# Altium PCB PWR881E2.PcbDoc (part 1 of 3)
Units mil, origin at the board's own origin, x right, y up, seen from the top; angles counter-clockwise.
Board outline 6500 x 3500 mil, 6 copper layers (Top Layer, Signal Layer 1, Signal Layer 2, Signal Layer 3, Signal Layer 4, Bottom Layer), stack 32.4 mil thick; 330 components, 152 nets, 836 pads, 570 vias.
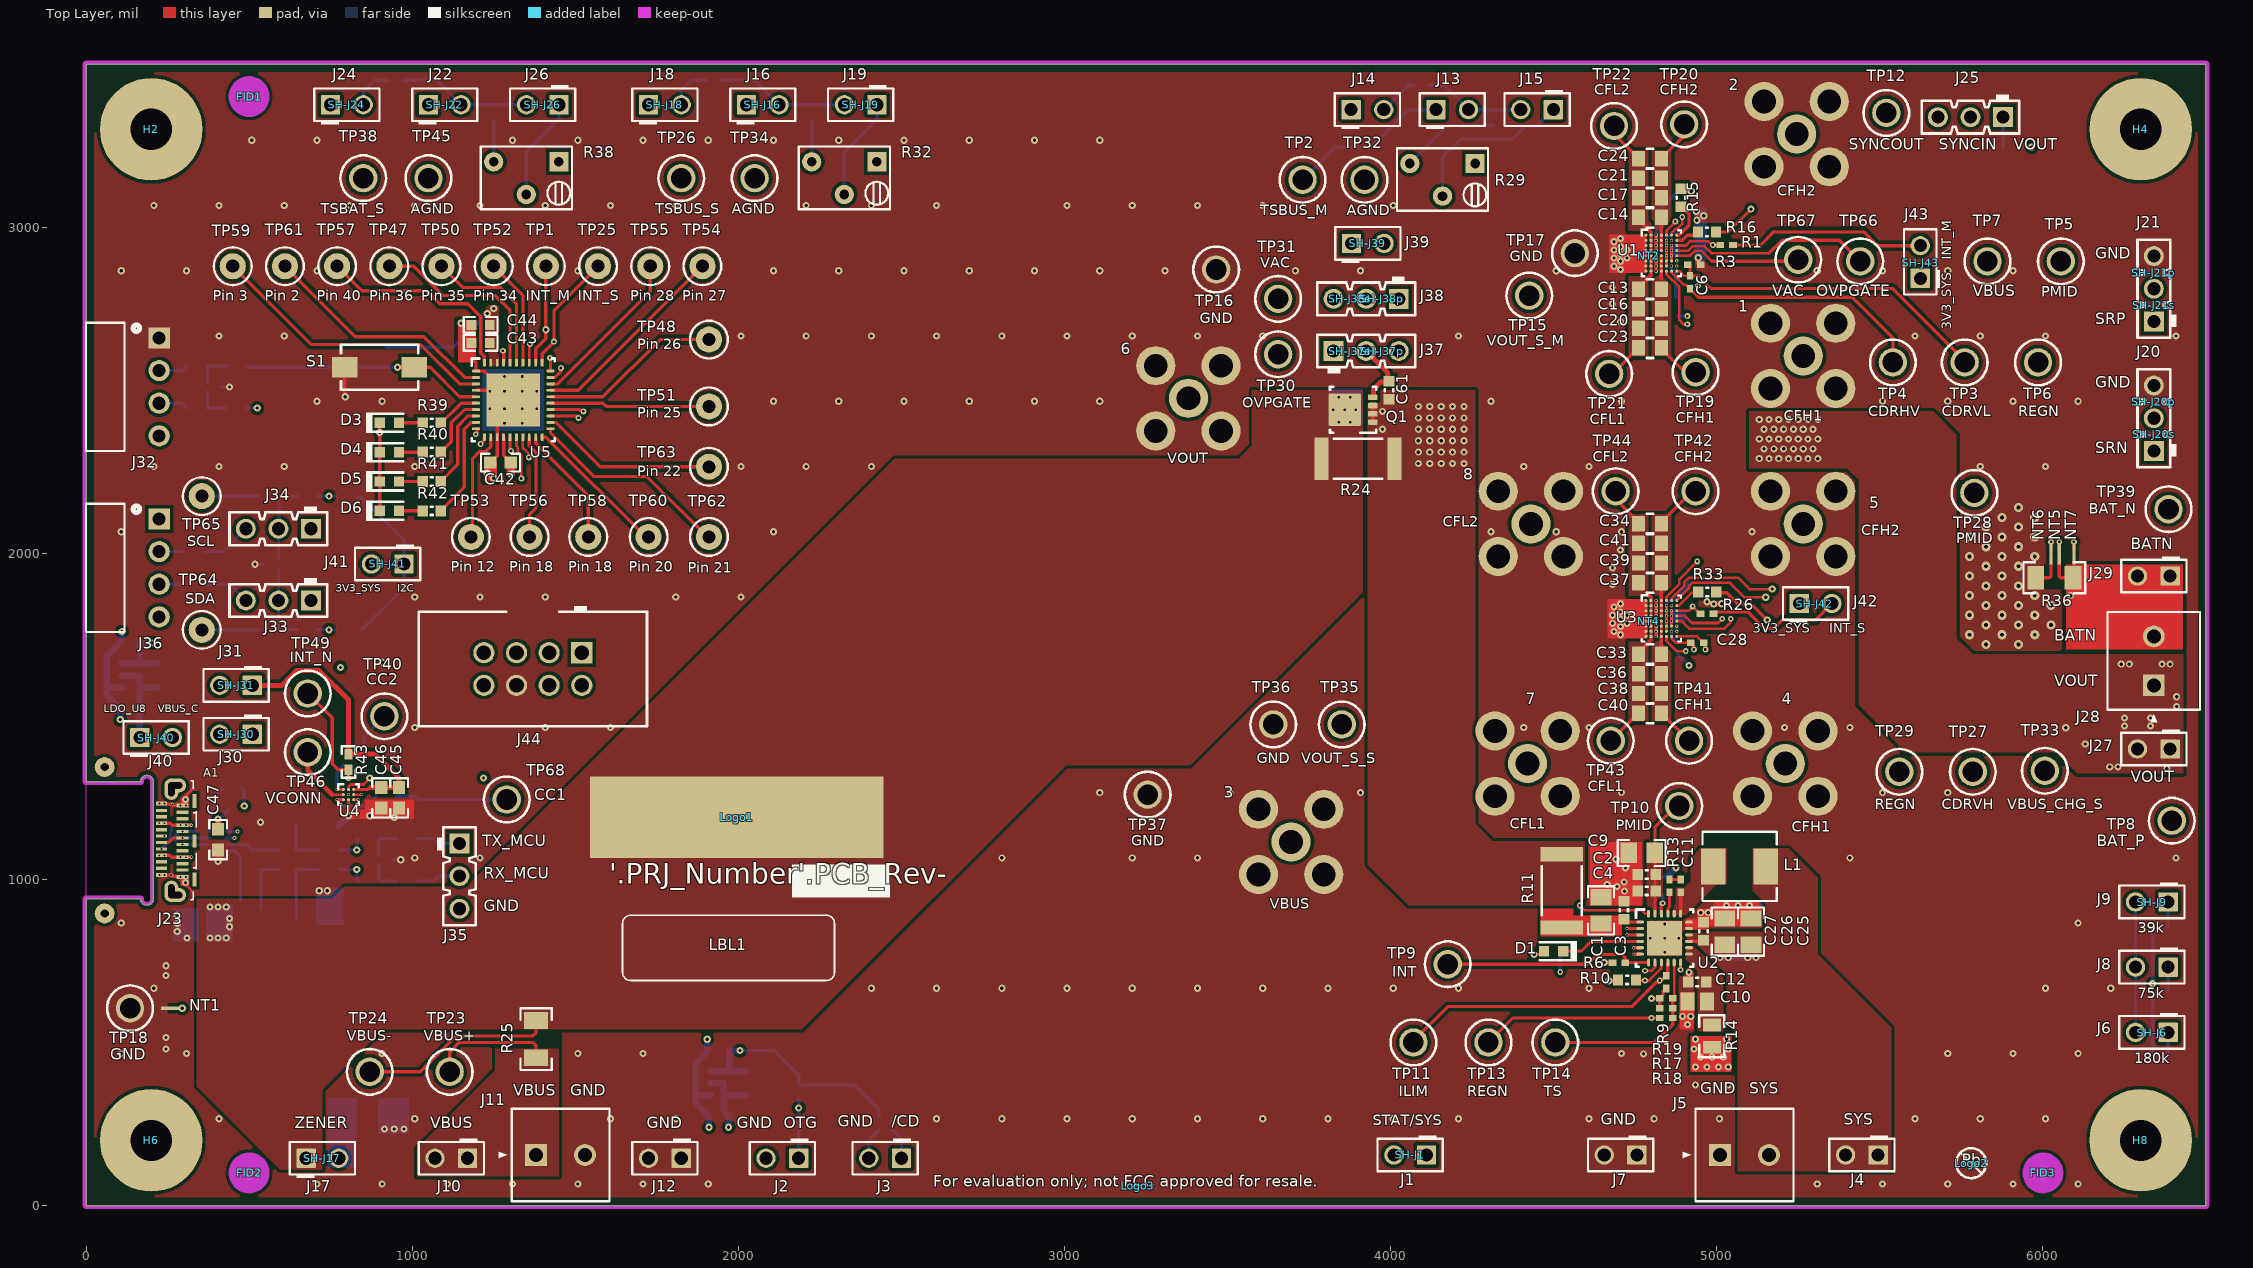
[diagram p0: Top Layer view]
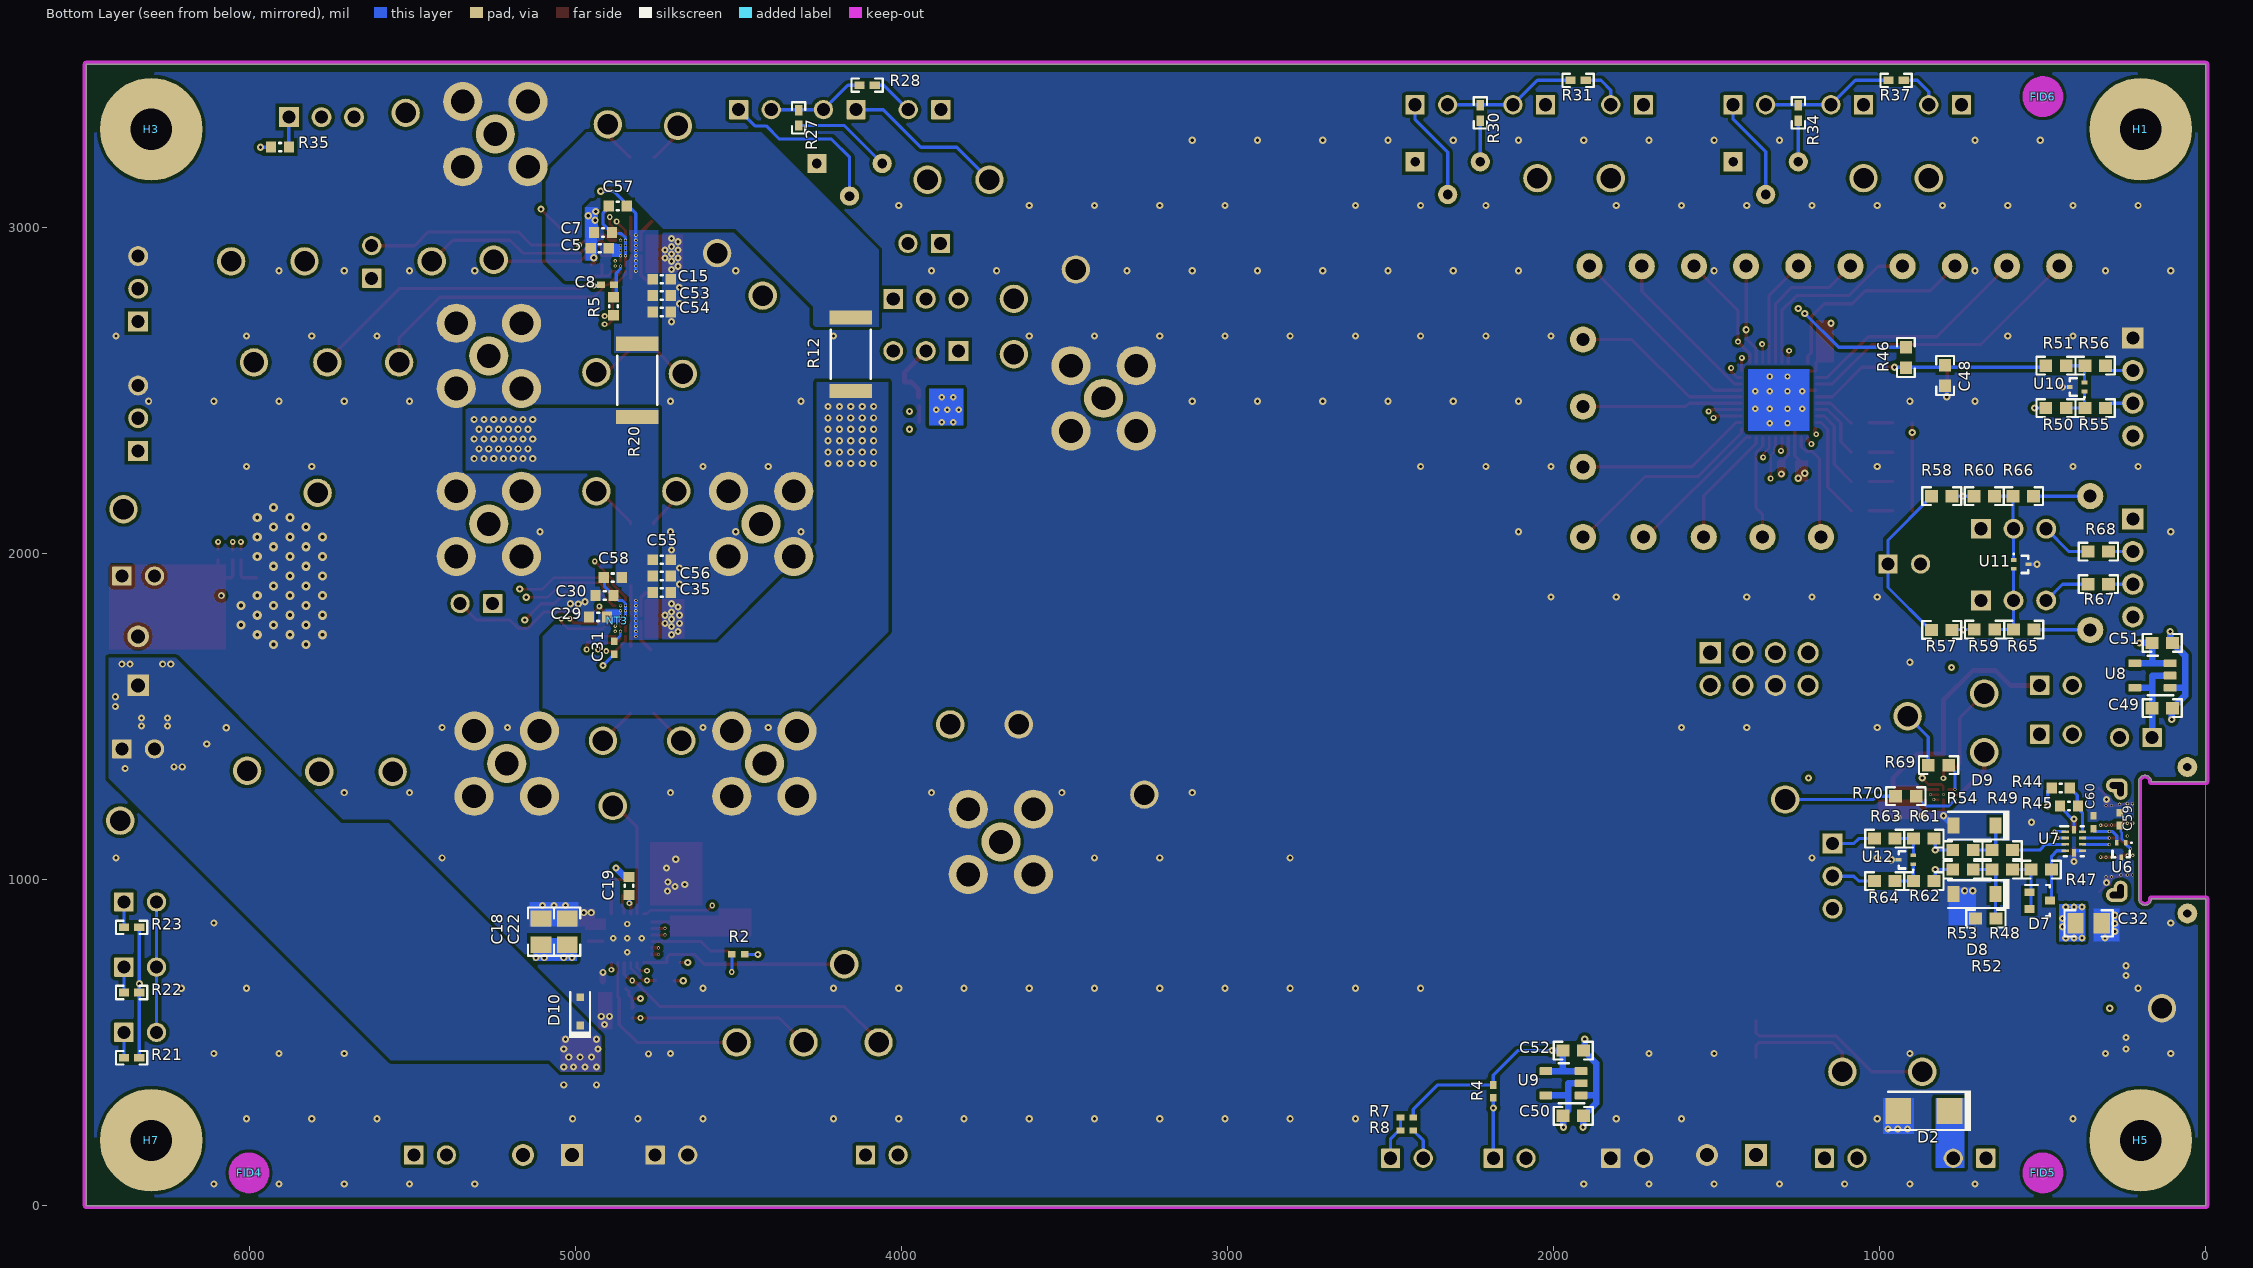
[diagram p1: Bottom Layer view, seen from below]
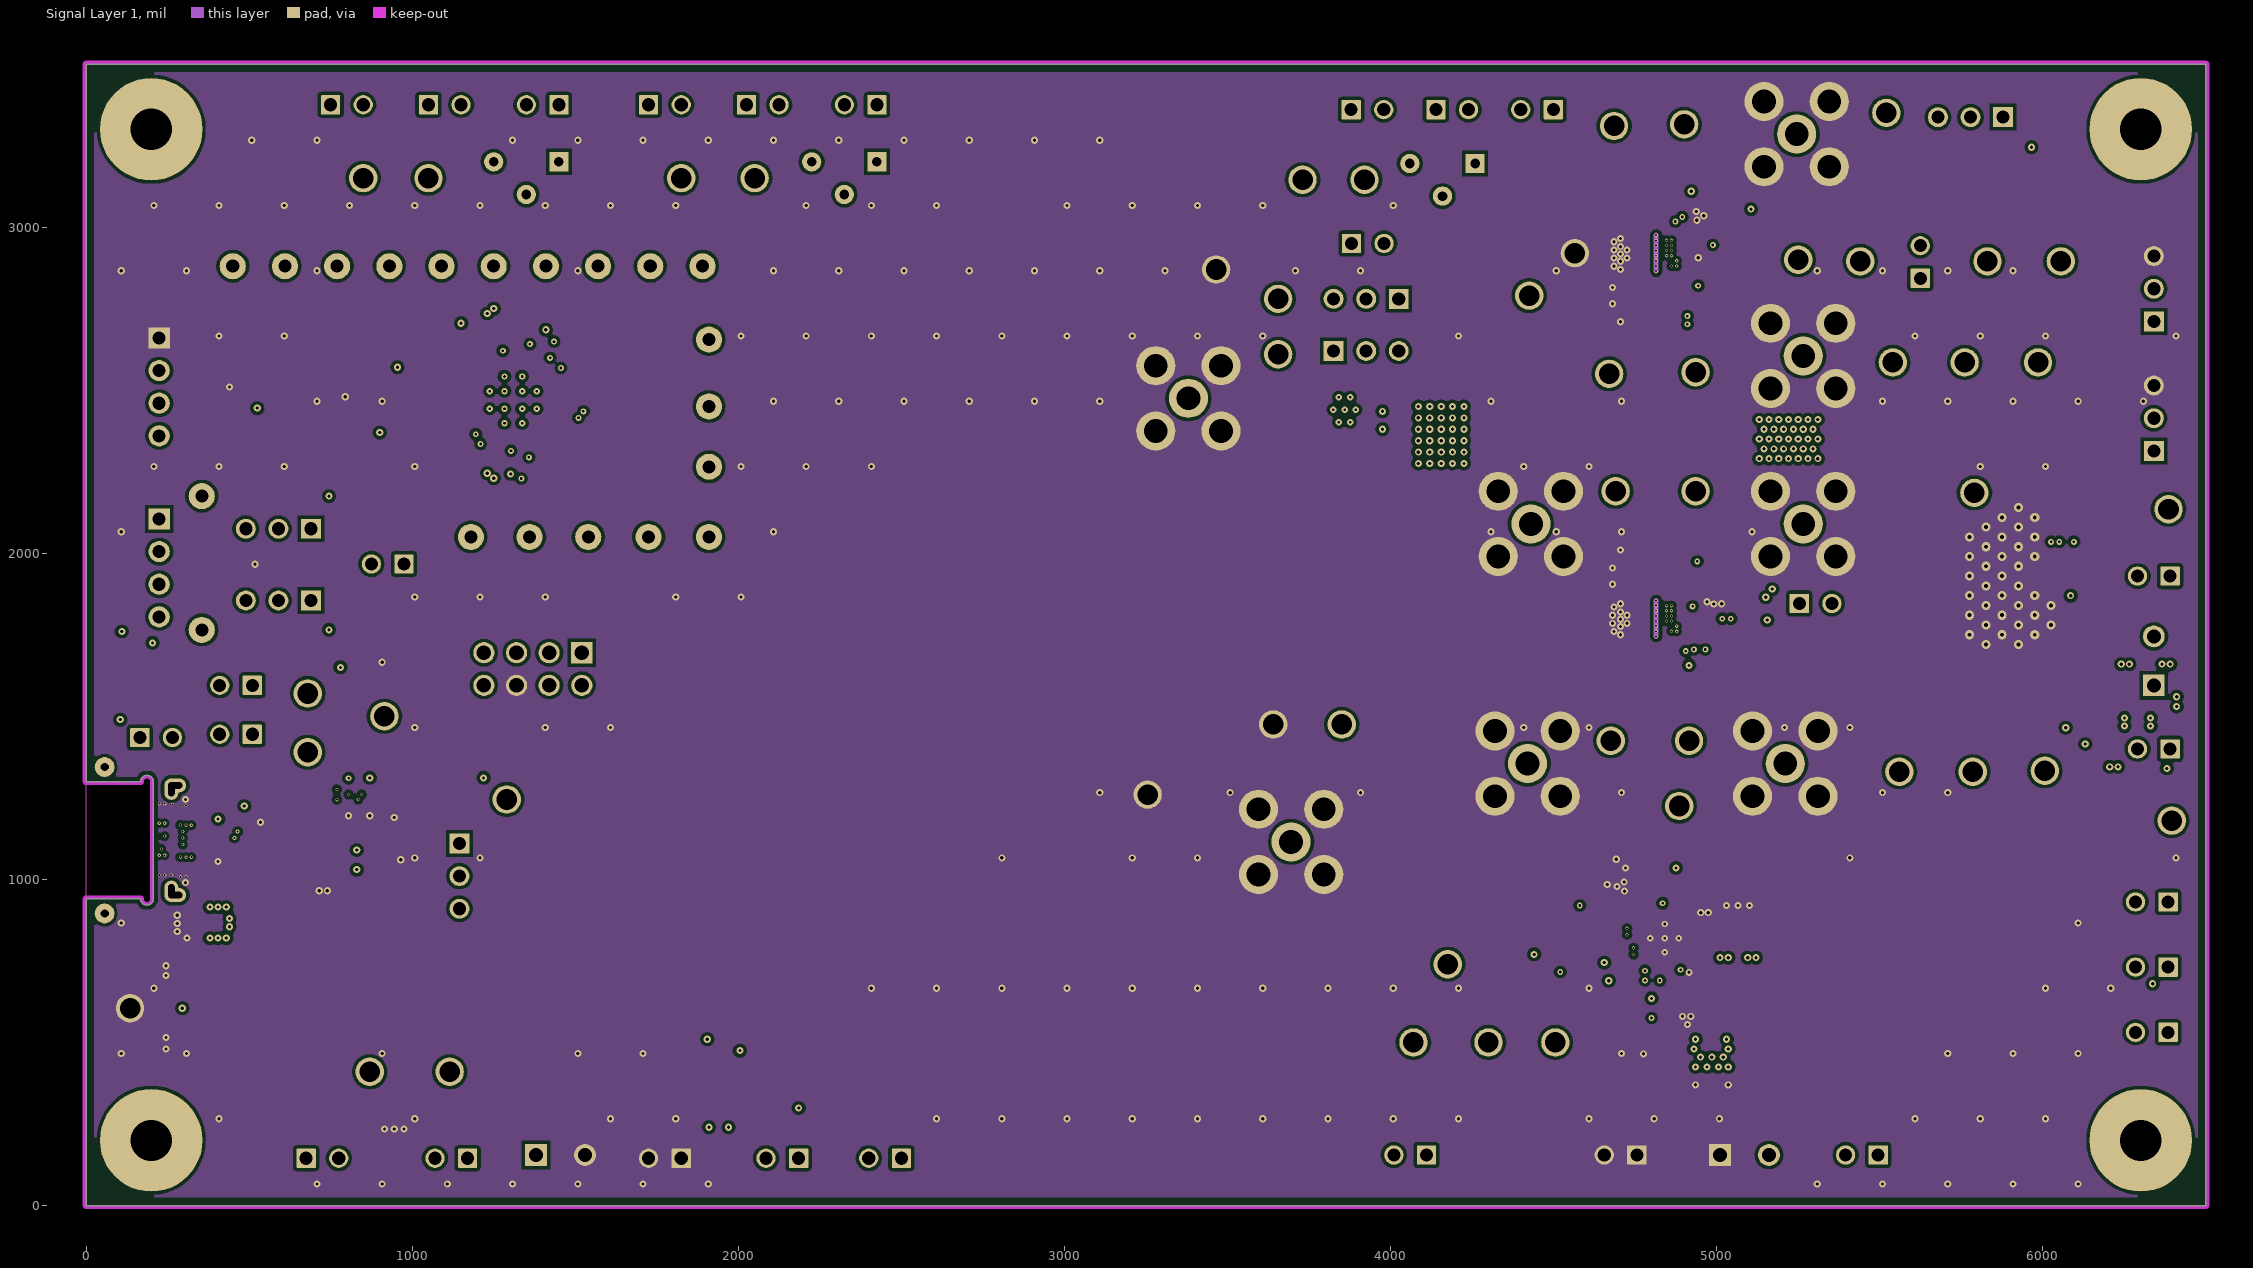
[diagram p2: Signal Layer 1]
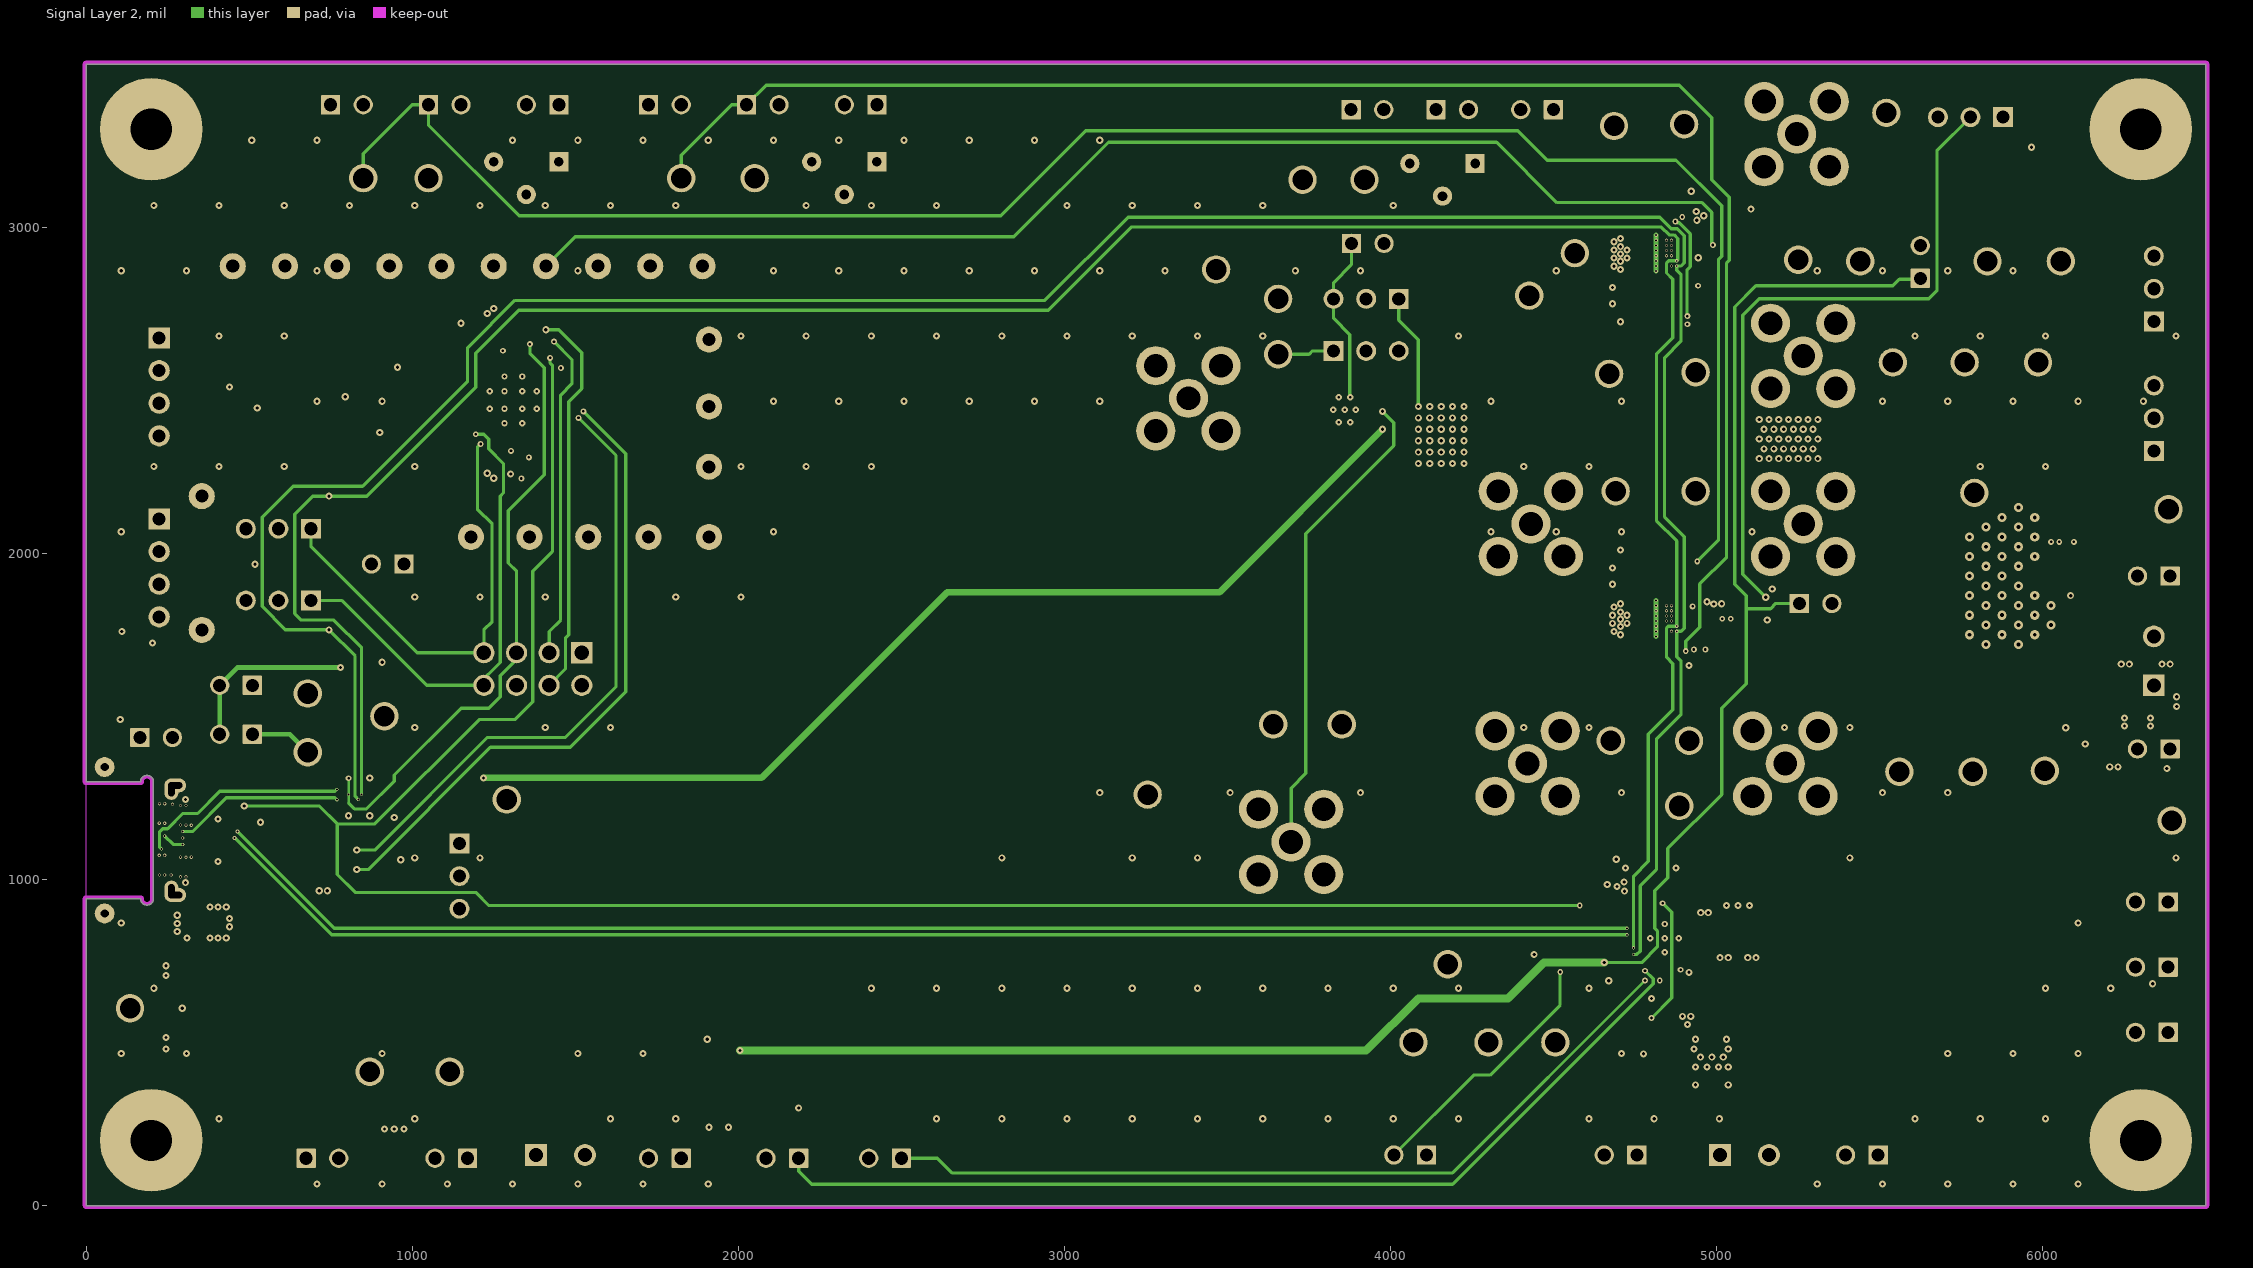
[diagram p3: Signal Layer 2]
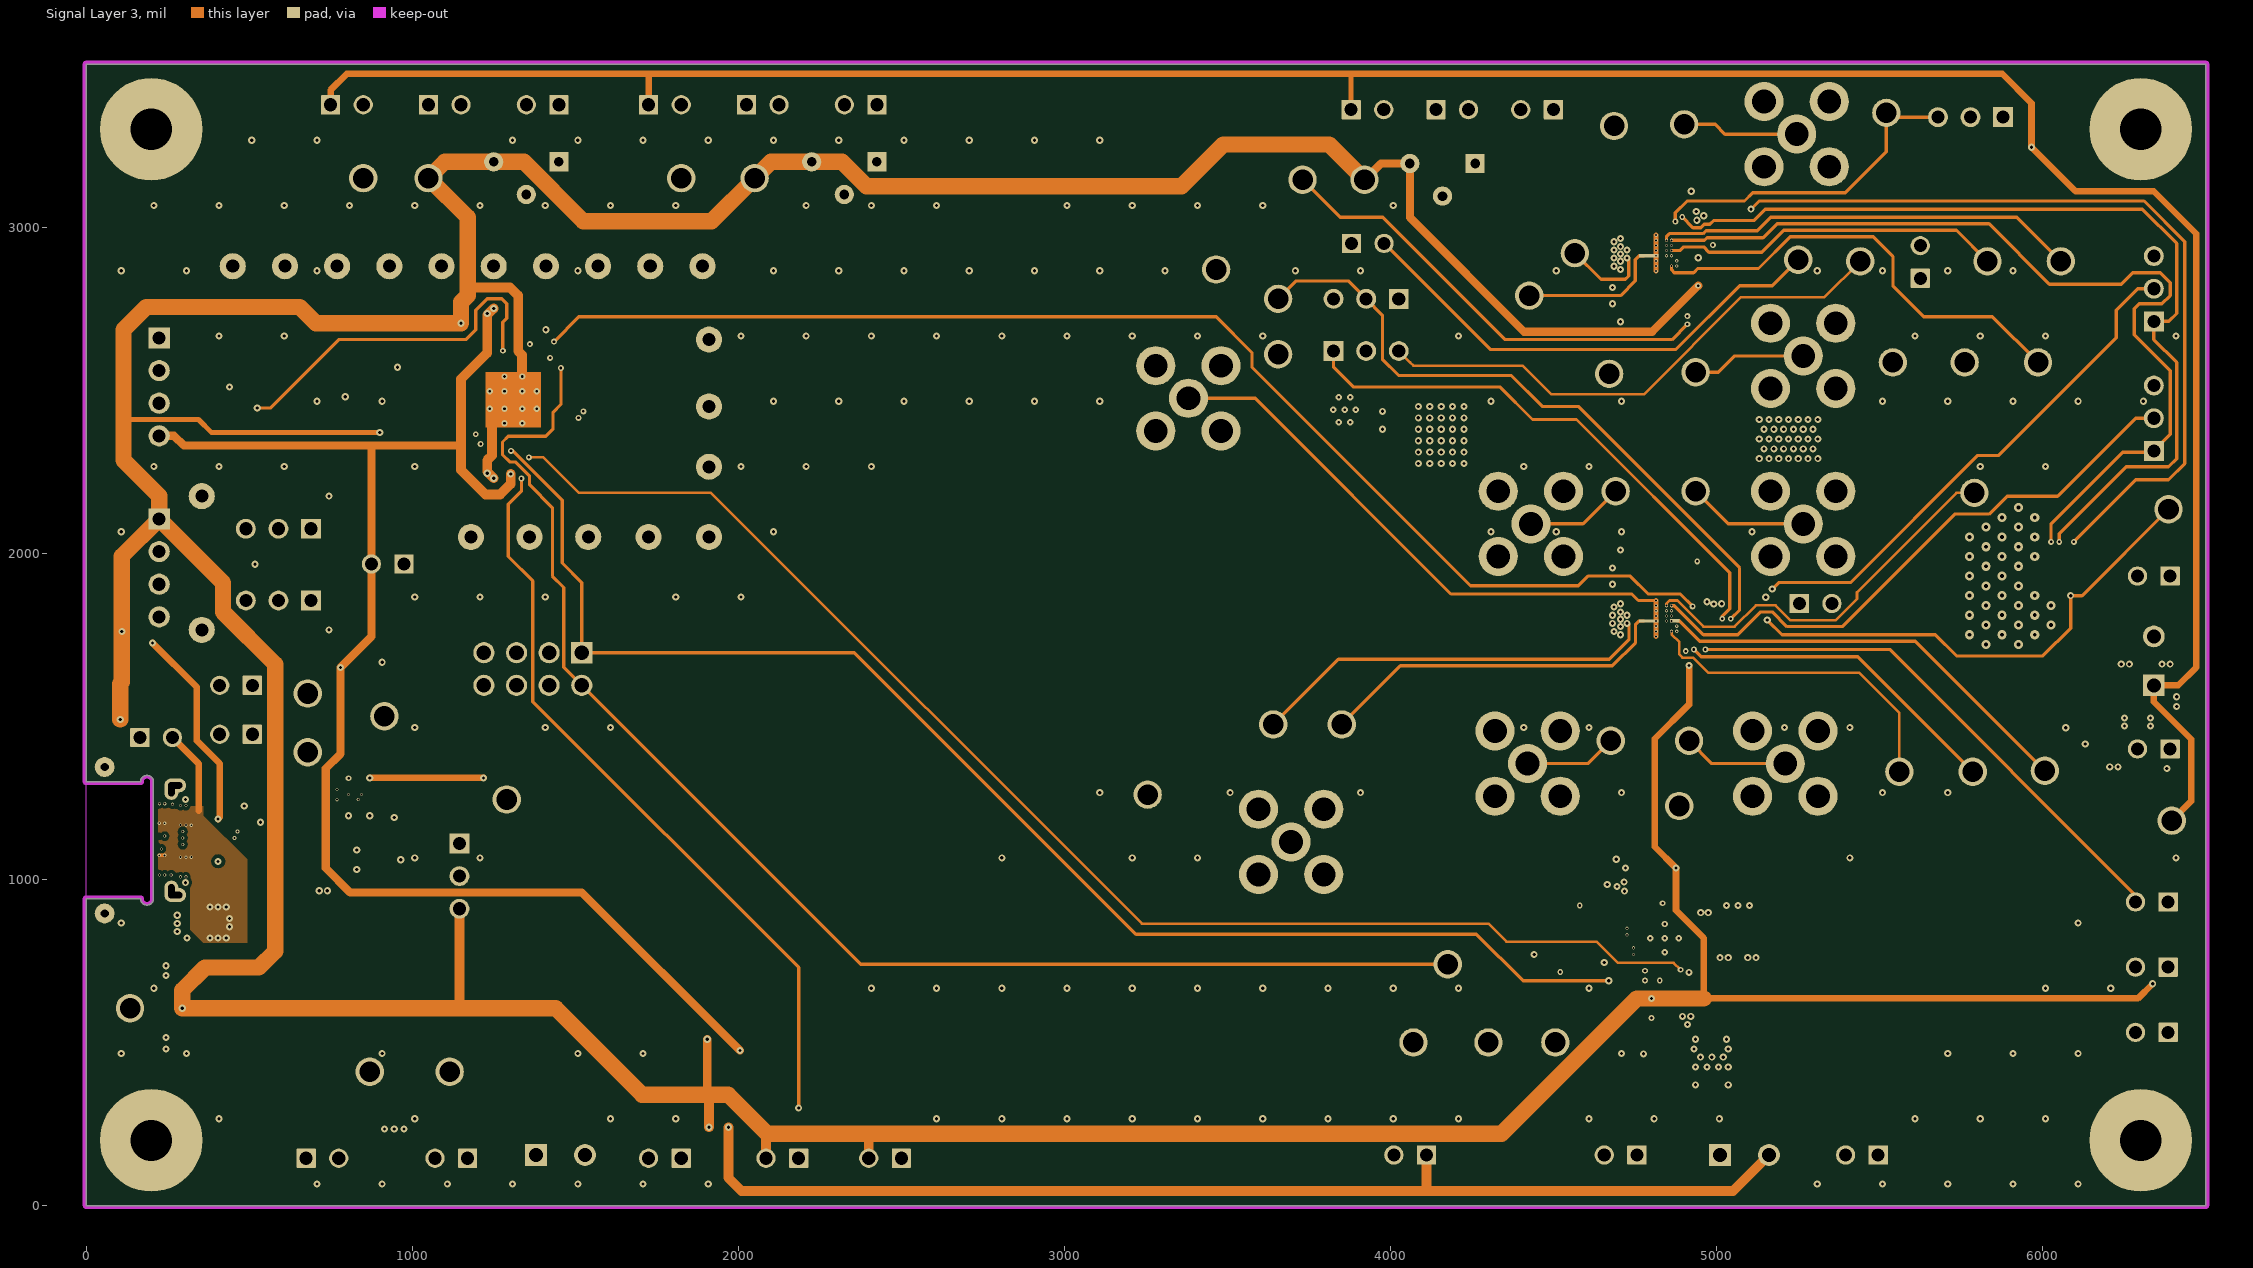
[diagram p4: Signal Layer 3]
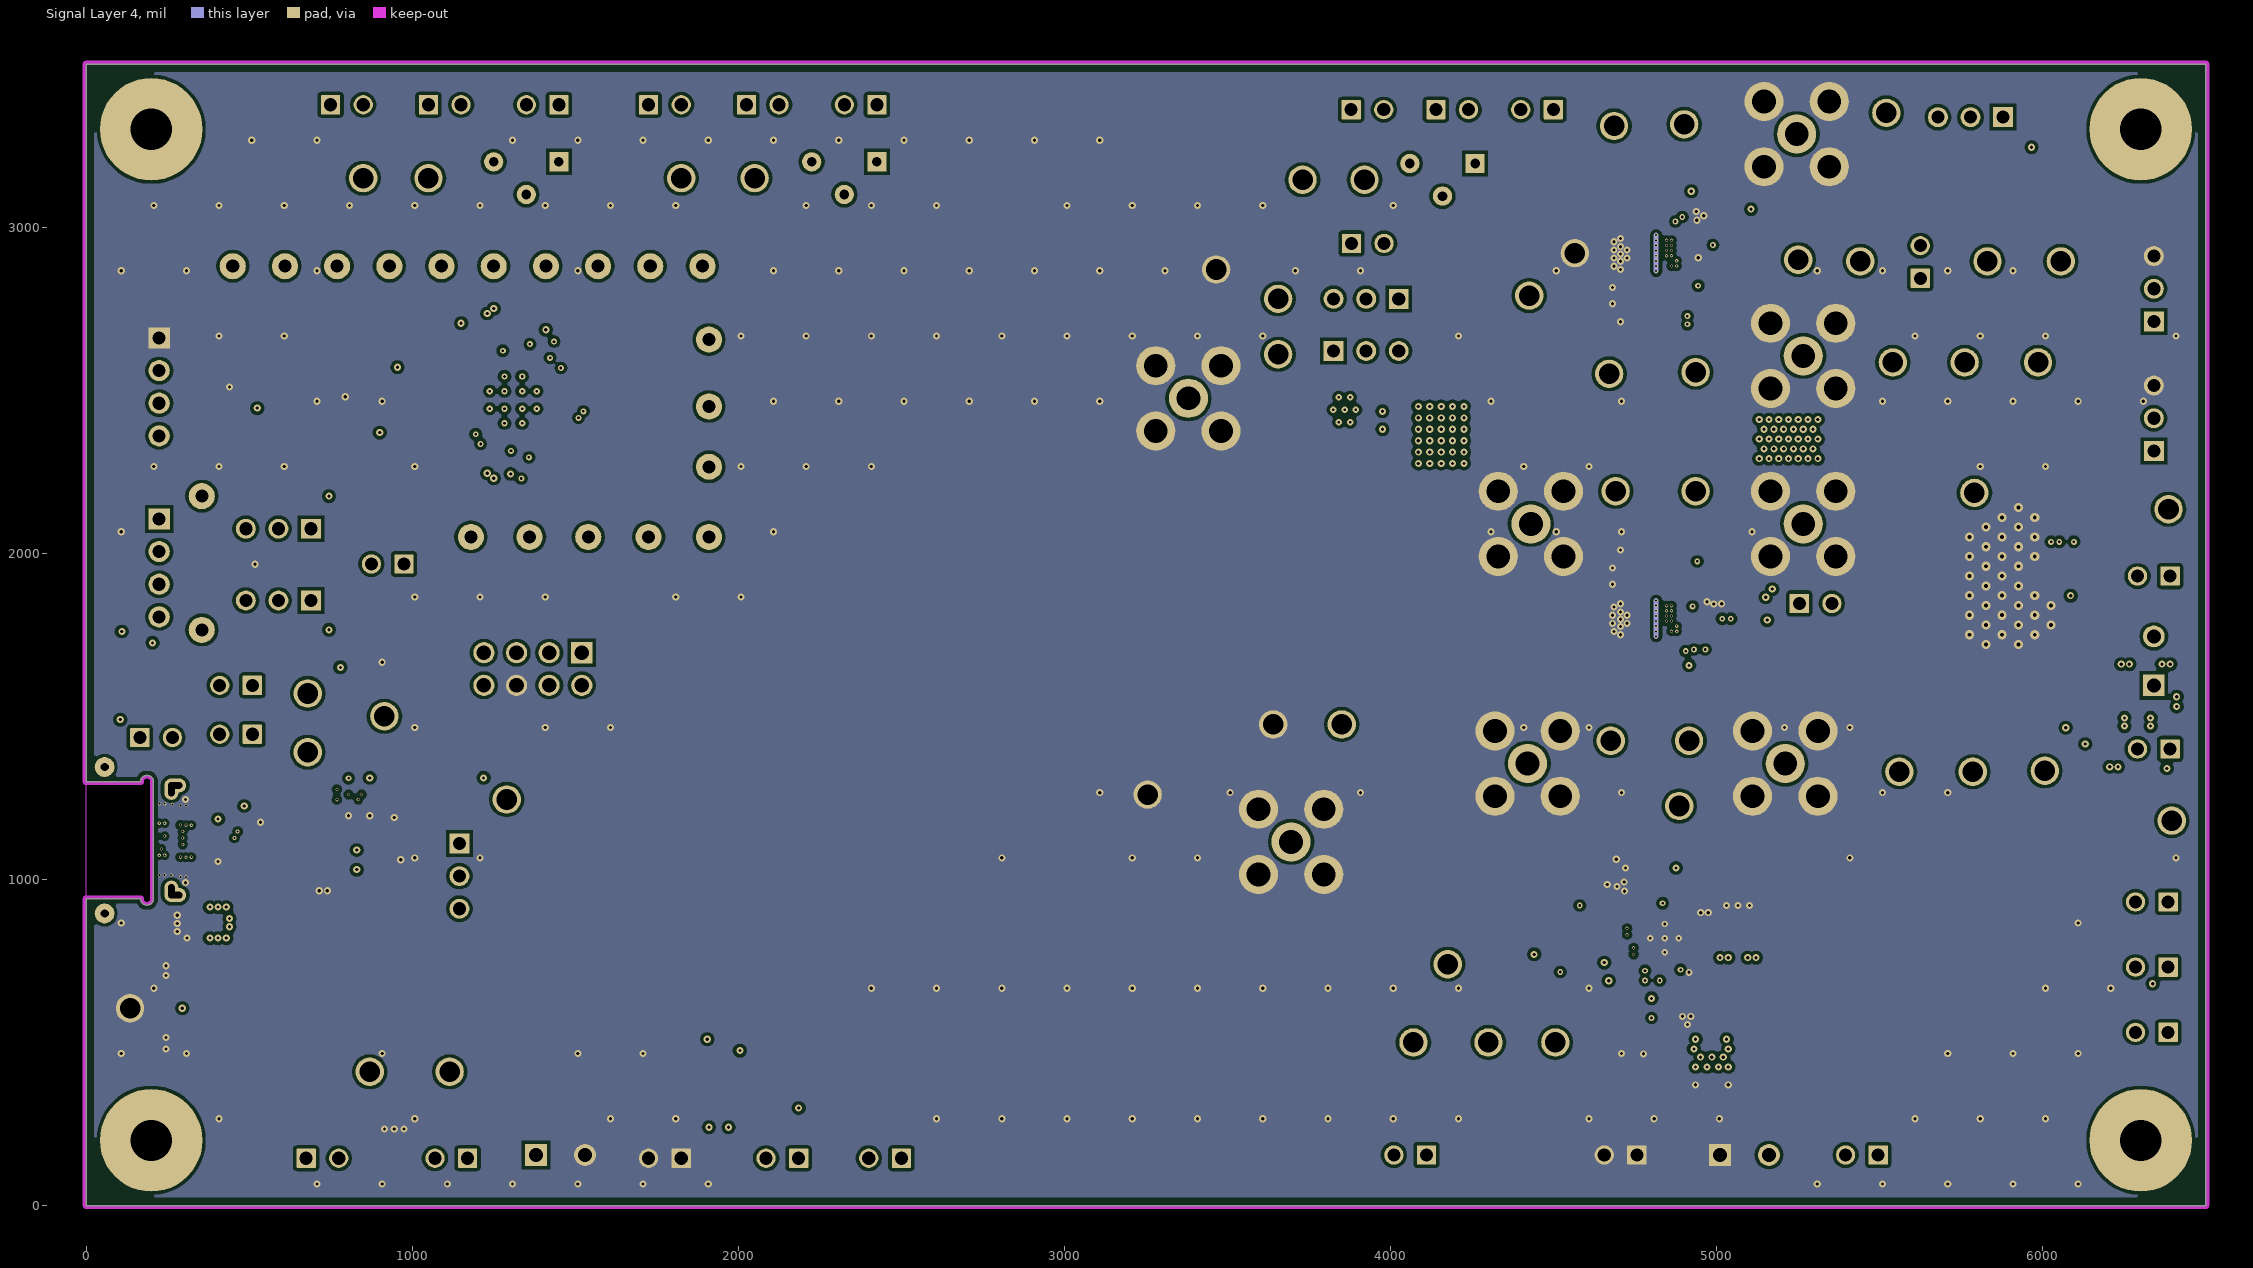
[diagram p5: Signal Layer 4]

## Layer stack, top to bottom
Top Solder: solder mask 0.4, Solder Resist, Dk 3.5
Top Layer: signal copper 1.4
Dielectric1: core 4.8, FR-4 High TG, Dk 4.8
Signal Layer 1: signal copper 1.4
Dielectric 2: prepreg 4.8, FR-4 High TG, Dk 4.8
Signal Layer 2: signal copper 1.4
Dielectric 3: core 4.8, FR-4 High TG, Dk 4.8
Signal Layer 3: signal copper 1.4
Dielectric 4: prepreg 4.8, FR-4 High TG, Dk 4.8
Signal Layer 4: signal copper 1.4
Dielectric 5: core 4.8, FR-4 High TG, Dk 4.8
Bottom Layer: signal copper 1.4
Bottom Solder: solder mask 0.4, Solder Resist, Dk 4.8

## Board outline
0,0 0,940.87 167.32,940.87 ccw(c187.01,940.87) 206.69,940.87 206.69,1299.13 ccw(c187.01,1299.13) 167.32,1299.13 0,1299.13 0,3500 6500,3500 6500,0

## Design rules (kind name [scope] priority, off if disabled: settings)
AcuteAngle [All] p1: minimum=4.50000000000000E+0001 checktracksonly=FALSE
AssemblyTestPointUsage [All] p1: valid=2
BoardOutlineClearance BoardOutlineClearance_J23 [InComponent('J23')] p1: gap=7.8
BoardOutlineClearance BoardOutlineClearance_MountingHoles [OnCopper and InComponentClass('Mounting Holes')] p2: gap=40
BoardOutlineClearance BoardOutlineClearance_Poly [OnCopper and IsPoly] p3: gap=15
BoardOutlineClearance [OnCopper and Not InComponentClass('Logo') and not InComponentClass('FiducialMark') and not InRegion(1000,500,4000,800) and not InPoly] p4: gap=12.8
Clearance Clearance_Keepouts [((IsTrack Or IsArc) And Not InPoly) And IsFree and IsKeepOut vs ((IsTrack Or IsArc) And Not InPoly) And IsFree and IsKeepOut] p1: gap=0
Clearance Clearance_Poly [InPolygon] p2: gap=10
Clearance [All] p3: gap=5.7
ComponentClearance ComponentClearance_NT [InComponent('NT*')] p1: gap=0 collisioncheckmode=3 verticalgap=0 showdistances=FALSE
ComponentClearance ComponentClearance_MountingHoles_FiducialMarks [InComponentClass('Mounting Holes') vs InComponentClass('FiducialMark')] p2: gap=50 collisioncheckmode=3 verticalgap=10 showdistances=FALSE
ComponentClearance ComponentClearance_Shunt [InComponentClass('Header')   or InComponentClass('Shunt') vs InComponentClass('Shunt')] p3: gap=0 collisioncheckmode=3 verticalgap=0 showdistances=FALSE
ComponentClearance ComponentClearance_Logo [InComponentClass('Logo')] p4: gap=50 collisioncheckmode=3 verticalgap=10 showdistances=FALSE
ComponentClearance ComponentClearance_ScrewToNut [(HasFootprint('NY PMS 440 0025 PH')) vs (HasFootprint('Keystone_1902C'))] p5: gap=5 collisioncheckmode=3 verticalgap=10 showdistances=FALSE
ComponentClearance ComponentClearance_MountingHoles [InComponentClass('Mounting Holes')] p6: gap=100 collisioncheckmode=3 verticalgap=100000 showdistances=FALSE
ComponentClearance ComponentClearance_SmallPassives [HasFootprint('0201*') or HasFootprint('0402*') or HasFootprint('0508') or HasFootprint('0603*') or HasFootprint('0612') or HasFootprint('0805*') or HasFootprint('0815*') or HasFootprint('0830*') or HasFootprint('1206*') or HasFootprint('1210*') or HasFootprint('1808*') or HasFootprint('1812*') or HasFootprint('1825*') or HasFootprint('2010*') or HasFootprint('2220*') or HasFootprint('2225*') or HasFootprint('2512*') or HasFootprint('2728*') or HasFootprint('3518*') vs HasFootprint('0201*') or HasFootprint('0402*') or HasFootprint('0508') or HasFootprint('0603*') or HasFootprint('0612') or HasFootprint('0805*') or HasFootprint('0815*') or HasFootprint('0830*') or HasFootprint('1206*') or HasFootprint('1210*') or HasFootprint('1808*') or HasFootprint('1812*') or HasFootprint('1825*') or HasFootprint('2010*') or HasFootprint('2220*') or HasFootprint('2225*') or HasFootprint('2512*') or HasFootprint('2728*') or HasFootprint('3518*')] p7: gap=5 collisioncheckmode=3 verticalgap=5 showdistances=FALSE
ComponentClearance ComponentClearance_THtoSMT [IsThruComponent vs IsSMTComponent] p8: gap=30 collisioncheckmode=3 verticalgap=30 showdistances=FALSE
ComponentClearance ComponentClearance_THtoTH [IsThruComponent vs IsThruComponent] p9: gap=30 collisioncheckmode=3 verticalgap=30 showdistances=FALSE
ComponentClearance [All] p10: gap=15 collisioncheckmode=3 verticalgap=15 showdistances=FALSE
DiffPairsRouting [All] p1: maxlimit=100 minlimit=10 mostfreqgap=10 toplayer_minwidth=15 toplayer_maxwidth=15 toplayer_prefwidth=15 midlayer1_minwidth=15 midlayer1_maxwidth=15 midlayer1_prefwidth=15 midlayer2_minwidth=15 midlayer2_maxwidth=15 midlayer2_prefwidth=15 midlayer3_minwidth=15 midlayer3_maxwidth=15 midlayer3_prefwidth=15 midlayer4_minwidth=15 midlayer4_maxwidth=15 midlayer4_prefwidth=15 bottomlayer_minwidth=15 bottomlayer_maxwidth=15 bottomlayer_prefwidth=15 maxuncoupledlength=1000
FabricationTestPointUsage TestPointUsage [All] p1: valid=2 allowmultiple=FALSE
FabricationTestpoint Testpoint [All] p1: side=3 testpointundercomponent=TRUE minsize=40 maxsize=100 preferedsize=60 minholesize=0 maxholesize=40 preferedholesize=32 testpointgrid=1 allowsidetop=TRUE allowsidebottom=TRUE usegrid=TRUE gridtolerance=0.01
FanoutControl Fanout_LCC [IsLCC] p1: bgadir=Out bgaviamode=Centered fanoutstyle=Auto fanoutdirection=Alternating viagrid=1 // Fanout_LCC (Default Rule)
FanoutControl Fanout_BGA [IsBGA] p2: bgadir=Out bgaviamode=Centered fanoutstyle=Auto fanoutdirection=Alternating viagrid=1 // Fanout_BGA (Default Rule)
FanoutControl Fanout_Default [All] p4: bgadir=Out bgaviamode=Centered fanoutstyle=Auto fanoutdirection=Alternating viagrid=1 // Fanout_Default (Default Rule)
FanoutControl Fanout_Small [(CompPinCount < 5)] p5: bgadir=Out bgaviamode=Centered fanoutstyle=Auto fanoutdirection=OutThenIn viagrid=1 // Fanout_Small (Default Rule)
HoleSize [All] p1: absolutevalues=TRUE maxlimit=251 minlimit=6 maxpercent=80.000 minpercent=20.000
HoleToHoleClearance HoleToHoleClearance_J23 [InComponent('J23') vs InComponent('J23')] p1: gap=0 allowstackedmicrovias=TRUE
HoleToHoleClearance [All] p2: gap=9.7 allowstackedmicrovias=TRUE
MinimumAnnularRing MinimumAnnularRing_ThermalPadVias [IsVia and InAnyComponent] p1: minimumring=5.91
MinimumAnnularRing [All] p2: minimumring=2
MinimumSolderMaskSliver MinimumSolderMaskSliver_YFF0056ACAJ [HasFootprint('YFF0056ACAJ')] p1: minsoldermaskwidth=3.7
MinimumSolderMaskSliver MinimumSolderMaskSliver_Logo [InComponentClass('Logo') vs InComponentClass('Logo')] p2: minsoldermaskwidth=0.7
MinimumSolderMaskSliver [All] p3: minsoldermaskwidth=3.94
PlaneConnect [All] p1: planeconnectstyle=Relief reliefexpansion=10 reliefentries=4 reliefconductorwidth=10 reliefairgap=10
PolygonConnect [All] p1: connectstyle=Direct reliefconductorwidth=10 reliefentries=4 polygonreliefangle="90 Angle" airgapwidth=10
RoutingVias ThermalPadVias [IsVia and InAnyComponent] p1: holewidth=7.87 width=19.68 viastyle="Through Hole" minholewidth=7.87 minwidth=19.68 maxholewidth=12.99 maxwidth=23.62
RoutingVias [All] p2: holewidth=10 width=22 viastyle="Through Hole" minholewidth=6 minwidth=6 maxholewidth=40 maxwidth=65
ShortCircuit ShortCircuit_j23 [InComponent('J23') vs InComponent('J23')] p1: allowed=TRUE
ShortCircuit [All] p2: allowed=FALSE
SilkToBoardRegionClearance [Not ((IsComment or IsDesignator) And (Hide <> 'False')) and not InRegion(1000,500,4000,800)] p1:
SilkToSilkClearance SilkToSilkClearance_Pb-FreeLogo [(HasFootprint('Pb-Free_Overlay_Medium') OR HasFootprint('Pb-Free_Overlay_Small')) vs (HasFootprint('Pb-Free_Overlay_Medium') OR HasFootprint('Pb-Free_Overlay_Small'))] p1: silktosilkclearance=0
SilkToSilkClearance [All] p2: silktosilkclearance=4
SilkToSolderMaskClearance SilkToComponentPadClearance [IsPad and InAnycomponent] p1: minsilkscreentomaskgap=4 clearancetoexposedcopper=TRUE
SilkToSolderMaskClearance "Silk to Solder Mask Opening" [All] p2: minsilkscreentomaskgap=4 clearancetoexposedcopper=FALSE
SolderMaskExpansion [All] p1: expansion=1.97
Width [All] p1: maxlimit=100 minlimit=7.8 preferedwidth=10 checkconnectedcopper=TRUE
13 further rules are at their usual default settings.

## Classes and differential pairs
component class "Mounting Holes": H2 H4 H6 H8
component class Logo: Logo1
component class PWR881E2_EVM_Hardware: FID1 FID2 FID3 FID4 FID5 FID6 H1 H2 H3 H4 H5 H6 H7 H8 LBL1 Logo1 Logo2 Logo3 SH-J1 SH-J6 SH-J9 SH-J16 SH-J17 SH-J18 SH-J19 SH-J20p SH-J20s SH-J21p SH-J21s SH-J22 SH-J24 SH-J26 SH-J30 SH-J31 SH-J37p SH-J37s SH-J38p SH-J38s SH-J39 SH-J40 SH-J41 SH-J42 SH-J43 ZZ1 ZZ2 ZZ3 ZZ4
component class FiducialMark: FID1 FID2 FID3 FID4 FID5 FID6
component class AssemblyNote: ZZ1 ZZ2 ZZ3 ZZ4
component class Label: LBL1
component class Header: J1 J2 J3 J4 J6 J7 J8 J9 J10 J12 J13 J14 J15 J16 J17 J18 J19 J20 J21 J22 J24 J25 J26 J27 J29 J30 J31 J33 J34 J35 J37 J38 J39 J40 J41 J42 J43
component class PWR881E2_MCU_USB: C42 C43 C44 C45 C46 C47 C48 C49 C50 C51 C52 C59 C60 D3 D4 D5 D6 D7 D8 D9 J30 J31 J32 J33 J34 J35 J36 J40 J41 J44 R39 R40 R41 R42 R43 R44 R45 R46 R47 R48 R49 R50 R51 R52 R53 R54 R55 R56 R57 R58 R59 R60 R61 R62 R63 R64 R65 R66 R67 R68 R69 R70 S1 TP40 TP46 TP47 TP48 TP49 TP50 TP51 TP52 TP53 TP54 TP55 TP56 TP57 TP58 TP59 TP60 TP61 TP62 TP63 TP64 TP65 TP68 U4 U5 U6 U7 U8 U9 U10 U11 U12
component class PWR881E2: 1 2 3 4 5 6 7 8 C1 C2 C3 C4 C5 C6 C7 C8 C9 C10 C11 C12 C13 C14 C15 C16 C17 C18 C19 C20 C21 C22 C23 C24 C25 C26 C27 C28 C29 C30 C31 C32 C33 C34 C35 C36 C37 C38 C39 C40 C41 C53 C54 C55 C56 C57 C58 C61 D1 D2 D10 J1 J2 J3 J4 J5 J6 J7 J8 J9 J10 J11 J12 J13 J14 J15 J16 J17 J18 J19 J20 J21 J22 J23 J24 J25 J26 J27 J28 J29 J37 J38 J39 J42 J43 L1 NT1 NT2 NT3 NT4 NT5 NT6 NT7 Q1 R1 R2 R3 R4 R5 R6 R7 R8 R9 R10 R11 R12 R13 R14 R15 R16 R17 R18 R19 R20 R21 R22 R23 R24 R25 R26 R27 R28 R29 R30 R31 R32 R33 R34 R35 R36 R37 R38 TP1 TP2 TP3 TP4 TP5 TP6 TP7 TP8 TP9 TP10 TP11 TP12 TP13 TP14 TP15 TP16 TP17 TP18 TP19 TP20 TP21 TP22 TP23 TP24 TP25 TP26 TP27 TP28 TP29 TP30 TP31 TP32 TP33 TP34 TP35 TP36 TP37 TP38 TP39 TP41 TP42 TP43 TP44 TP45 TP66 TP67 U1 U2 U3
component class Shunt: SH-J1 SH-J6 SH-J9 SH-J16 SH-J17 SH-J18 SH-J19 SH-J20p SH-J20s SH-J21p SH-J21s SH-J22 SH-J24 SH-J26 SH-J30 SH-J31 SH-J37p SH-J37s SH-J38p SH-J38s SH-J39 SH-J40 SH-J41 SH-J42 SH-J43

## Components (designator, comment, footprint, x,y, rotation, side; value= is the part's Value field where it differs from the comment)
1 "CFH1" PROBE 5265,2605 r90 top
2 "CFH2" PROBE 5245,3285 r90 top
3 "VBUS" PROBE 3695,1115 r90 top
4 "CFH1" PROBE 5210,1355 r90 top
5 "CFH2" PROBE 5265,2090 r90 top
6 "VOUT" PROBE 3380,2475 r90 top
7 "CFL1" PROBE 4420,1355 r90 top
8 "CFL2" PROBE 4430,2090 r90 top
C1 "GRM219R71E105KA88D" 0805_HV 4645,905 r90 top
C2 "GRM188R61E106MA73D" 0603L 4785,1015 r180 top
C3 "GRM1885C1E102JA01D" 0603L 4715,905 r90 top
C4 "GRM188R61E106MA73D" 0603L 4785,965 r180 top
C5 "GRM188R61E105KA12D" 0603L 4925,2935 r180 bottom
C6 "GRM155R71C224KA12D" 0402L 4918,2831 r90 top
C7 "GRM188D71A106MA73D" 0603L 4915,2983 r0 bottom
C8 "GRM155R61A475MEAAD" 0402L 4901,2823 r0 bottom
C9 "GRM21BR61E226ME44L" 0805_HV 4770,1081 r180 top
C10 "GRM21BR71A106KE51L" 0805L 4940,625 r180 top
C11 "GRM155R71E473KA88D" 0402L 4890,980 r270 top
C12 "C1608X7R1C105K080AC" 0603L 4940,685 r180 top
C13 "GRMJN7R61C206ME05" 0704 4795,2810 r180 top
C14 "GRMJN7R61C206ME05" 0704 4795,3030 r180 top
C15 "GRM188R61A226ME15D" 0603L 4735,2840 r180 bottom
C16 "GRMJN7R61C206ME05" 0704 4795,2750 r180 top
C17 "GRMJN7R61C206ME05" 0704 4795,3090 r180 top
C18 "GRM21BR71A106KE51L" 0805_HV 5105,840 r90 bottom
C19 "GRM188R61C475KAAJ" 0603L 4835,980 r90 bottom
C20 "GRMJN7R61C206ME05" 0704 4795,2690 r180 top
C21 "GRMJN7R61C206ME05" 0704 4795,3150 r180 top
C22 "GRM21BR71A106KE51L" 0805_HV 5025,840 r90 bottom
C23 "GRMJN7R61C206ME05" 0704 4795,2630 r180 top
C24 "GRMJN7R61C206ME05" 0704 4795,3210 r180 top
C25 "GRM21BR71A106KE51L" 0805_HV 5105,840 r90 top
C26 "GRM21BR71A106KE51L" 0805_HV 5025,840 r90 top
C27 "C1608X7R1E104K080AA" 0603L 4959,841 r90 top
C28 "GRM155R71C224KA12D" 0402L 4940,1725 r0 top
C29 "GRM188R61E105KA12D" 0603L 4930,1805 r180 bottom
C30 "GRM188D71A106MA73D" 0603L 4910,1870 r0 bottom
C31 "GRM155R61A475MEAAD" 0402L 4880,1710 r270 bottom
C32 "C2012X5R1E106K125AB" 0805_HV 360,865 r180 bottom
C33 "GRMJN7R61C206ME05" 0704 4795,1690 r180 top
C34 "GRMJN7R61C206ME05" 0704 4795,2090 r180 top
C35 "GRM188R61A226ME15D" 0603L 4735,1880 r180 bottom
C36 "GRMJN7R61C206ME05" 0704 4795,1630 r180 top
C37 "GRMJN7R61C206ME05" 0704 4795,1910 r180 top
C38 "GRMJN7R61C206ME05" 0704 4795,1570 r180 top
C39 "GRMJN7R61C206ME05" 0704 4795,1970 r180 top
C40 "GRMJN7R61C206ME05" 0704 4795,1510 r180 top
C41 "GRMJN7R61C206ME05" 0704 4795,2030 r180 top
C42 "C1608X7R1E104K080AA" 0603 1271,2278 r180 top
C43 "C1608X7R1E104K080AA" 0603_HV 1210,2645 r180 top
C44 "C1608X7R1E104K080AA" 0603_HV 1210,2700 r180 top
C45 "GRM188D71A106MA73D" 0603 960,1250 r270 top
C46 "C1608X7R1E104K080AA" 0603 905,1250 r270 top
C47 "C1608X7R1E104K080AA" 0603 405,1122 r90 top
C48 "GRM188R71E102KA01D" 0603 800,2545 r270 bottom
C49 "GRM188R71E105KA12D" 0603 134,1525 r180 bottom
C50 "GRM188R71E105KA12D" 0603 1940,275 r180 bottom
C51 "GRM188R61C475KAAJ" 0603 134,1725 r180 bottom
C52 "GRM188R61C475KAAJ" 0603 1940,475 r180 bottom
C53 "GRM188R61A226ME15D" 0603L 4735,2790 r180 bottom
C54 "GRM188R61A226ME15D" 0603L 4735,2740 r180 bottom
C55 "GRM188R61A226ME15D" 0603L 4735,1980 r180 bottom
C56 "GRM188R61A226ME15D" 0603L 4735,1930 r180 bottom
C57 "GRM188D71A106MA73D" 0603L 4870,3065 r0 bottom
C58 "GRM188D71A106MA73D" 0603L 4885,1925 r0 bottom
C59 "GRM155R71H271KA01D" 0402L 265,1185 r90 bottom
C60 "GRM155R71H271KA01D" 0402L 345,1175 r90 bottom
C61 "GRM188R71E103KA01D" 0603L 3995,2500 r90 top
D1 "LTST-C190GKT" LED_LTST-C190 4500,780 r0 top
D2 "SMAJ13A" SMA 865,290 r0 bottom
D3 "LTST-C190GKT" LED_LTST-C190 930,2400 r180 top
D4 "LTST-C190GKT" LED_LTST-C190 930,2310 r180 top
D5 "LTST-C190GKT" LED_LTST-C190 930,2220 r180 top
D6 "LTST-C190GKT" LED_LTST-C190 930,2130 r180 top
D7 "BAV99W-7-F" SOT-323 510,935 r180 bottom
D8 "MMSZ5227B-7-F" SOD-123 710,955 r0 bottom
D9 "MMSZ5227B-7-F" SOD-123 710,1165 r0 bottom
D10 "SP4021-01FTG" SOD-323 4985,595 r90 bottom
FID1 "Fiducial" Fiducial10-30 500,3400 r0 top
FID2 "Fiducial" Fiducial10-30 500,100 r0 top
FID3 "Fiducial" Fiducial10-30 6000,100 r0 top
FID4 "Fiducial" Fiducial10-30 6000,100 r90 bottom
FID5 "Fiducial" Fiducial10-30 500,100 r90 bottom
FID6 "Fiducial" Fiducial10-30 500,3400 r90 bottom
H1 "1902C" Keystone_1902C 200,3300 r180 bottom locked
H2 "NY PMS 440 0025 PH" "NY PMS 440 0025 PH" 200,3300 r0 top locked
H3 "1902C" Keystone_1902C 6300,3300 r180 bottom locked
H4 "NY PMS 440 0025 PH" "NY PMS 440 0025 PH" 6300,3300 r0 top locked
H5 "1902C" Keystone_1902C 200,200 r180 bottom locked
H6 "NY PMS 440 0025 PH" "NY PMS 440 0025 PH" 200,200 r0 top locked
H7 "1902C" Keystone_1902C 6300,200 r180 bottom locked
H8 "NY PMS 440 0025 PH" "NY PMS 440 0025 PH" 6300,200 r0 top locked
J1 "STAT/SYS" CONN_PEC02SAAN 4060,155 r180 top
J2 "PEC02SAAN" CONN_PEC02SAAN 2135,145 r180 top
J3 "PEC02SAAN" CONN_PEC02SAAN 2450,145 r180 top
J4 "PEC02SAAN" CONN_PEC02SAAN 5445,155 r180 top
J5 "1727010" PhoenixConact_1727010 5085,155 r0 top
J6 "180k" CONN_PEC02SAAN 6334,531 r180 top
J7 "PEC02SAAN" CONN_PEC02SAAN 4705,155 r180 top
J8 "75k" CONN_PEC02SAAN 6334,731 r180 top
J9 "39k" CONN_PEC02SAAN 6334,931 r180 top
J10 "PEC02SAAN" CONN_PEC02SAAN 1120,145 r180 top
J11 "1727010" PhoenixConact_1727010 1455,155 r0 top
J12 "PEC02SAAN" CONN_PEC02SAAN 1775,145 r180 top
J13 "PEC02SAAN" CONN_PEC02SAAN 4189,3360 r0 top
J14 "PEC02SAAN" CONN_PEC02SAAN 3929,3360 r0 top
J15 "PEC02SAAN" CONN_PEC02SAAN 4449,3360 r180 top
J16 "PEC02SAAN" CONN_PEC02SAAN 2075,3375 r0 top
J17 "PEC02SAAN" CONN_PEC02SAAN 725,145 r0 top
J18 "PEC02SAAN" CONN_PEC02SAAN 1775,3375 r0 top
J19 "PEC02SAAN" CONN_PEC02SAAN 2375,3375 r180 top
J20 "TSW-103-07-T-S" Samtec_TSW-103-07-T-S 6340,2414 r90 top
J21 "TSW-103-07-T-S" Samtec_TSW-103-07-T-S 6340,2811 r90 top
J22 "PEC02SAAN" CONN_PEC02SAAN 1100,3375 r0 top
J23 "20-0000016-01" Lintes_20-0000016-01 0,1120 r270 top locked
J24 "PEC02SAAN" CONN_PEC02SAAN 800,3375 r0 top
J25 "TSW-103-07-T-S" Samtec_TSW-103-07-T-S 5778,3337 r180 top
J26 "PEC02SAAN" CONN_PEC02SAAN 1400,3375 r180 top
J27 "PEC02SAAN" CONN_PEC02SAAN 6340,1400 r180 top
J28 "1727010" PhoenixConact_1727010 6340,1670 r90 top
J29 "PEC02SAAN" CONN_PEC02SAAN 6340,1930 r180 top
J30 "PEC02SAAN" CONN_PEC02SAAN 460,1445 r180 top
J31 "PEC02SAAN" CONN_PEC02SAAN 460,1595 r180 top
J32 "22-05-3041" CONN_22-05-3041 0,2510 r270 top
J33 "TSW-103-07-T-S" Samtec_TSW-103-07-T-S 590,1855 r180 top
J34 "TSW-103-07-T-S" Samtec_TSW-103-07-T-S 590,2075 r180 top
J35 "TSW-103-07-T-S" Samtec_TSW-103-07-T-S 1145,1010 r270 top
J36 "22-05-3041" CONN_22-05-3041 0,1955 r270 top
J37 "TSW-103-07-T-S" Samtec_TSW-103-07-T-S 3925,2620 r0 top
J38 "TSW-103-07-T-S" Samtec_TSW-103-07-T-S 3925,2780 r180 top
J39 "PEC02SAAN" CONN_PEC02SAAN 3930,2950 r0 top
J40 "PEC02SAAN" CONN_PEC02SAAN 215,1435 r0 top
J41 "PEC02SAAN" CONN_PEC02SAAN 925,1967 r180 top
J42 "PEC02SAAN" CONN_PEC02SAAN 5303,1846 r0 top
J43 "PEC02SAAN" CONN_PEC02SAAN 5624,2893 r90 top
J44 "70246-0801" Molex_70246-0801 1370,1645 r270 top
L1 "IHLP2020BZER1R0M11" IHLP-2020BZ 5070,1040 r0 top
LBL1 "Size: 0.65\" x 0.20 \"" Label_650x200 1970,790 r0 top
Logo1 "Texas Instruments" TI_Stacked_SolderMask_Small 1995,1190 r0 top
Logo2 "Pb-Free Symbol" Pb-Free_Overlay_Small 5780,130 r0 top
Logo3 "FCC disclaimer" FCC_disclaimer 3225,60 r0 top
NT1 "Net-Tie" Net-Tie_10milWide_30milLong#1 260,605 r0 top net-tie
NT2 "Net-Tie" Net-Tie_10milWide_30milLong#2 4792,2912 r180 top net-tie
NT3 "Net-Tie" Net-Tie_10milWide_30milLong#3 4879,1793 r0 bottom net-tie
NT4 "Net-Tie" Net-Tie_10milWide_30milLong#2 4792,1792 r180 top net-tie
NT5 "Net-Tie" Net-Tie_10milWide_30milLong#1 6050,1995 r90 top net-tie
NT6 "Net-Tie" Net-Tie_10milWide_30milLong#1 6025,1995 r90 top net-tie
NT7 "Net-Tie" Net-Tie_10milWide_30milLong#1 6095,1995 r90 top net-tie
Q1 "CSD17575Q3" DQG0008A 3885,2440 r180 top
R1 "CRCW040210K0JNED" 0402L 5030,2945 r0 top
R2 "CRCW04022K21FKED" 0402L 4500,770 r0 bottom
R3 "CRCW040218K0JNED" 0402L 4931,2884 r0 top
R4 "CRCW040210K0JNED" 0402L 2185,350 r90 bottom
R5 "RC0603FR-071KL" 0603L 4883,2757 r270 bottom
R6 "CRCW040210K0JNED" 0402L 4700,745 r180 top
R7 "CRCW040210K0JNED" 0402L 2450,270 r180 bottom
R8 "CRCW040210K0JNED" 0402L 2450,230 r0 bottom
R9 "CRCW0402130RFKED" 0402L 4845,685 r270 top
R10 "RC0603FR-071KL" 0603L 4725,692 r0 top
R11 "CRCW25120000Z0EGHP" 2512L 4525,965 r90 top
R12 "CRCW25120000Z0EGHP" 2512L 4155,2610 r270 bottom
R13 "CRCW04020000Z0ED" 0402L 4855,980 r270 top
R14 "5106" 5106 4985,520 r270 top
R15 "CRCW0603100RJNEA" 0603L 4890,3090 r90 top
R16 "CRCW0603100RJNEA" 0603L 4970,2985 r0 top
R17 "CRCW040230K1FKED" 0402L 4845,605 r0 top
R18 "CRCW04025K23FKED" 0402L 4845,575 r0 top
R19 "CRCW040210K0JNED" 0402L 4845,635 r0 top
R20 "CRCW25120000Z0EGHP" 2512L 4810,2530 r270 bottom
R21 "CRCW0402180KJNED" 0402 6360,453 r0 bottom
R22 "CRCW040275K0JNED" 0402 6360,653 r0 bottom
R23 "CRCW040239K0JNED" 0402 6360,853 r0 bottom
R24 "CRCW25120000Z0EGHP" 2512L 3900,2290 r0 top
R25 "WSLP1206R0100FEA" 1206 1380,510 r270 top
R26 "CRCW040210K0JNED" 0402L 4970,1815 r0 top
R27 "CRCW040210K0JNED" 0402 4315,3335 r90 bottom
R28 "CRCW040210K0JNED" 0402 4105,3435 r180 bottom
R29 "3266W-1-104LF" TRIM_3266W 4259,3195 r270 top
R30 "CRCW040210K0JNED" 0402 2225,3350 r90 bottom
R31 "CRCW040210K0JNED" 0402 1925,3450 r180 bottom
R32 "3266W-1-104LF" TRIM_3266W 2425,3200 r270 top
R33 "CRCW0603100RJNEA" 0603L 4971,1881 r0 top
R34 "CRCW040210K0JNED" 0402 1250,3350 r90 bottom
R35 "CRCW0603100RJNEA" 0603L 5905,3245 r180 bottom
R36 "CSNL1206FT2L00" 1206 6035,1925 r0 top
R37 "CRCW040210K0JNED" 0402 950,3450 r180 bottom
R38 "3266W-1-104LF" TRIM_3266W 1450,3200 r270 top
R39 "RC0603FR-072K2L" 0603L 1060,2400 r0 top
R40 "RC0603FR-072K2L" 0603L 1060,2310 r0 top
R41 "RC0603FR-072K2L" 0603L 1060,2220 r0 top
R42 "RC0603FR-072K2L" 0603L 1060,2130 r0 top
R43 "CRCW0402200KJNED" 0402 805,1360 r90 top
R44 "RC0603FR-07100RL" 0603L 445,1280 r0 bottom
R45 "RC0603FR-0710KL" 0603L 420,1225 r180 bottom
R46 "RC0603FR-0747KL" 0603 920,2600 r90 bottom
R47 "RC0603JR-070RL" 0603 505,1030 r0 bottom
R48 "RC0603FR-07100RL" 0603 625,1030 r0 bottom
R49 "RC0603FR-07100RL" 0603 625,1090 r0 bottom
R50 "RC0603FR-07100RL" 0603 460,2445 r180 bottom
R51 "RC0603FR-07100RL" 0603 460,2575 r180 bottom
R52 "RC0603FR-0710KL" 0603 675,880 r180 bottom
R53 "RT0603DRE07499RL" 0603 745,1030 r0 bottom
R54 "RT0603DRE07499RL" 0603 745,1090 r0 bottom
R55 "RC0603FR-07100RL" 0603 340,2445 r180 bottom
R56 "RC0603FR-07100RL" 0603 340,2575 r180 bottom
R57 "RC0603FR-074K7L" 0603 810,1765 r180 bottom
R58 "RC0603FR-074K7L" 0603 810,2175 r180 bottom
R59 "RC0603FR-07100RL" 0603 679,1766 r180 bottom
R60 "RC0603FR-07100RL" 0603 680,2175 r180 bottom
R61 "RC0603FR-07100RL" 0603 865,1125 r0 bottom
R62 "RC0603FR-07100RL" 0603 865,995 r0 bottom
R63 "RC0603FR-07100RL" 0603 985,1125 r0 bottom
R64 "RC0603FR-07100RL" 0603 985,995 r0 bottom
R65 "RC0603FR-071KL" 0603 559,1766 r180 bottom
R66 "RC0603FR-071KL" 0603 560,2175 r180 bottom
R67 "RC0603FR-07100RL" 0603 330,1905 r180 bottom
R68 "RC0603FR-07100RL" 0603 330,2005 r180 bottom
R69 "RC0603FR-071KL" 0603 820,1350 r180 bottom
R70 "RC0603FR-071KL" 0603 920,1255 r180 bottom
S1 "ADTSM31NV" SW_ADTSM31N 900,2570 r0 top
SH-J1 "969102-0000-DA" SNT-100-BK-G 4060,155 r0 top
SH-J6 "969102-0000-DA" SNT-100-BK-G 6335,530 r0 top
SH-J9 "969102-0000-DA" SNT-100-BK-G 6335,930 r0 top
SH-J16 "969102-0000-DA" SNT-100-BK-G 2075,3375 r0 top
SH-J17 "969102-0000-DA" SNT-100-BK-G 725,145 r0 top
SH-J18 "969102-0000-DA" SNT-100-BK-G 1775,3375 r0 top
SH-J19 "969102-0000-DA" SNT-100-BK-G 2375,3375 r0 top
SH-J20p "969102-0000-DA" SNT-100-BK-G 6340,2465 r90 top
SH-J20s "969102-0000-DA" SNT-100-BK-G 6340,2365 r90 top
SH-J21p "969102-0000-DA" SNT-100-BK-G 6340,2860 r90 top
SH-J21s "969102-0000-DA" SNT-100-BK-G 6340,2760 r90 top
SH-J22 "969102-0000-DA" SNT-100-BK-G 1100,3375 r0 top
SH-J24 "969102-0000-DA" SNT-100-BK-G 800,3375 r0 top
SH-J26 "969102-0000-DA" SNT-100-BK-G 1400,3375 r0 top
SH-J30 "969102-0000-DA" SNT-100-BK-G 460,1445 r0 top
SH-J31 "969102-0000-DA" SNT-100-BK-G 460,1595 r0 top
SH-J37p "969102-0000-DA" SNT-100-BK-G 3975,2620 r0 top
SH-J37s "969102-0000-DA" SNT-100-BK-G 3875,2620 r0 top
SH-J38p "969102-0000-DA" SNT-100-BK-G 3975,2780 r0 top
SH-J38s "969102-0000-DA" SNT-100-BK-G 3875,2780 r0 top
SH-J39 "969102-0000-DA" SNT-100-BK-G 3930,2950 r0 top
SH-J40 "969102-0000-DA" SNT-100-BK-G 215,1435 r0 top
SH-J41 "969102-0000-DA" SNT-100-BK-G 925,1967 r180 top
SH-J42 "969102-0000-DA" SNT-100-BK-G 5300,1845 r0 top
SH-J43 "969102-0000-DA" SNT-100-BK-G 5625,2890 r90 top
TP1 "INT_M" Keystone5002 1410,2880 r0 top
TP2 "TSBUS_M" Keystone5012#1 3730,3145 r90 top
TP3 "CDRVL" Keystone5012#1 5760,2585 r0 top
TP4 "CDRHV" Keystone5012#1 5540,2585 r0 top
TP5 "PMID" Keystone5012#1 6055,2895 r0 top
TP6 "REGN" Keystone5012#1 5985,2585 r0 top
TP7 "VBUS" Keystone5012#1 5830,2895 r0 top
TP8 "BAT_P" Keystone5012#1 6395,1180 r0 top
TP9 "INT" Keystone5012#1 4175,740 r0 top
TP10 "PMID" Keystone5012#1 4885,1225 r0 top
TP11 "ILIM" Keystone5012#1 4070,500 r0 top
TP12 "SYNCOUT" Keystone5012#1 5520,3350 r0 top
TP13 "REGN" Keystone5012#1 4300,500 r0 top
TP14 "TS" Keystone5012#1 4505,500 r0 top
TP15 "VOUT_S_M" Keystone5012#1 4425,2790 r0 top
TP16 "GND" Keystone5012#1 3465,2870 r0 top
TP17 "GND" Keystone5012#1 4565,2920 r0 top
TP18 "GND" Keystone5012#1 135,605 r0 top
TP19 "CFH1" Keystone5012#1 4935,2555 r0 top
TP20 "CFH2" Keystone5012#1 4900,3315 r0 top
TP21 "CFL1" Keystone5012#1 4670,2550 r0 top
TP22 "CFL2" Keystone5012#1 4685,3310 r90 top
TP23 "VBUS+" Keystone5012#1 1115,410 r0 top
TP24 "VBUS-" Keystone5012#1 870,410 r0 top
TP25 "INT_S" Keystone5002 1570,2880 r270 top
TP26 "TSBUS_S" Keystone5012#1 1825,3150 r0 top
TP27 "CDRVH" Keystone5012#1 5785,1330 r0 top
TP28 "PMID" Keystone5012#1 5790,2185 r0 top
TP29 "REGN" Keystone5012#1 5560,1330 r0 top
TP30 "OVPGATE" Keystone5012#1 3655,2610 r0 top
TP31 "VAC" Keystone5012#1 3655,2780 r0 top
TP32 "AGND" Keystone5012#1 3920,3145 r180 top
TP33 "VBUS_CHG_S" Keystone5012#1 6006,1333 r0 top
TP34 "AGND" Keystone5012#1 2050,3150 r180 top
TP35 "VOUT_S_S" Keystone5012#1 3850,1475 r0 top
TP36 "GND" Keystone5012#1 3640,1475 r0 top
TP37 "GND" Keystone5012#1 3255,1260 r0 top
TP38 "TSBAT_S" Keystone5012#1 850,3150 r0 top
TP39 "BAT_N" Keystone5012#1 6385,2135 r0 top
TP40 "CC2" Keystone5012#1 915,1500 r0 top
TP41 "CFH1" Keystone5012#1 4915,1425 r0 top
TP42 "CFH2" Keystone5012#2 4975,2135 r0 top
TP43 "CFL1" Keystone5012#1 4675,1425 r90 top
TP44 "CFL2" Keystone5012#1 4690,2190 r0 top
TP45 "AGND" Keystone5012#1 1050,3150 r270 top
TP46 "VCONN" Keystone5012#1 680,1390 r0 top
TP47 "Pin 36" Keystone5002 930,2880 r0 top
TP48 "Pin 26" Keystone5002 1910,2655 r0 top
TP49 "INT_N" Keystone5012#1 680,1570 r0 top
TP50 "Pin 35" Keystone5002 1090,2880 r0 top
TP51 "Pin 25" Keystone5002 1910,2450 r0 top
TP52 "Pin 34" Keystone5002 1250,2880 r0 top
TP53 "Pin 12" Keystone5002 1180,2050 r0 top
TP54 "Pin 27" Keystone5002 1890,2880 r0 top
TP55 "Pin 28" Keystone5002 1730,2880 r0 top
TP56 "Pin 18" Keystone5002 1360,2050 r0 top
TP57 "Pin 40" Keystone5002 770,2880 r0 top
TP58 "Pin 18" Keystone5002 1540,2050 r0 top
TP59 "Pin 3" Keystone5002 450,2880 r0 top
TP60 "Pin 20" Keystone5002 1725,2050 r0 top
TP61 "Pin 2" Keystone5002 610,2880 r0 top
TP62 "Pin 21" Keystone5002 1910,2050 r0 top
TP63 "Pin 22" Keystone5002 1910,2265 r0 top
TP64 "SDA" Keystone5004 355,1765 r0 top
TP65 "SCL" Keystone5002 355,2175 r0 top
TP66 "OVPGATE" Keystone5012#1 5440,2895 r0 top
TP67 "VAC" Keystone5012#1 5250,2900 r0 top
TP68 "CC1" Keystone5012#1 1290,1245 r0 top
U1 "BQ25970YFFR" YFF0056ACAJ 4830,2920 r0 top locked
U2 "BQ25890RTWR" RTW0024H 4840,820 r0 top
U3 "BQ25970YFFR" YFF0056ACAJ 4830,1800 r0 top
U4 "TUSB422YFF" YFF0009AJAK 805,1260 r0 top
U5 "MSP430G2955IRHA40R" RHA0040B 1310,2470 r0 top
U6 "TPD2EUSB30DRTR" DRT0003A 260,1090 r0 bottom
U7 "TS3USB221RSER" RSE0010A 405,1117 r180 bottom
U8 "TLV70433DBVR" DBV0005A_N 164,1625 r0 bottom
U9 "TLV70433DBVR" DBV0005A_N 1970,375 r0 bottom
U10 "TPD2EUSB30ADRTR" DRT0003A 395,2510 r90 bottom
U11 "TPD2EUSB30ADRTR" DRT0003A 567,1966 r270 bottom
U12 "TPD2EUSB30ADRTR" DRT0003A 920,1060 r90 bottom
ZZ1 "This Assembly Note is for PCB labels only" AssemblyNoteLabel 205,4038 r0 top
ZZ2 "These assemblies are ESD sensitive, ESD precautions shall be observed." AssemblyNote 205,3929.11 r0 top
ZZ3 "These assemblies must be clean and free from flux and all contaminants. Use of no clean flux is not acceptable." AssemblyNote 205,3840.56 r0 top
ZZ4 "These assemblies must comply with workmanship standards IPC-A-610 Class 2, unless otherwise specified." AssemblyNote 205,3752 r0 top

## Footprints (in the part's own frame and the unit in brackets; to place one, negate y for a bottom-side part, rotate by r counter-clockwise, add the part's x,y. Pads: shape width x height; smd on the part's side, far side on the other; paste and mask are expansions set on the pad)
0402 [mm] "0402 from SM-752 data"
  rect 0.8x0.6 smd: 1(-0.6,0) 2(0.6,0)
  silkscreen extent -1.22,-0.52 1.22,0.52, body extent -0.55,-0.3 0.55,0.3, height 0.6
0402L [mm] "0402 from SM-752 data"
  rect 0.6x0.5 smd: 1(-0.5,0) 2(0.5,0)
  body extent -0.55,-0.3 0.55,0.3, height 0.6
0603 [mm] "0603 from SM-752 data"
  rect 1x0.95 smd: 1(-0.8,0) 2(0.8,0)
  silkscreen extent -1.52,-0.69 1.52,0.69, body extent -0.87,-0.47 0.87,0.47, height 1
0603_HV [mil] "Ernesto recommended land pattern.  26 mil between pads."
  rect 30x30 smd: 1(-28,0) 2(28,0)
  silkscreen extent -52,-24 52,24, body extent -34,-19 34,19, height 39
0603L [mm] "0603 from SM-752 data"
  rect 0.8x0.85 smd: 1(-0.7,0) 2(0.7,0)
  silkscreen extent -0.07,-0.33 0.07,0.33, body extent -0.87,-0.47 0.87,0.47, height 1
0704 [mm] "Murata"
  rrect11% 1x1.2 smd: 1(-0.9,0) 2(0.9,0)
  silkscreen extent -0.25,-0.77 0.25,0.8, body extent -0.95,-0.55 0.95,0.55, height 0.8
0805_HV [mil] "0805 with 30mil clearance between pads"
  rect 50x63 smd: 1(-40,0) 2(40,0)
  silkscreen extent -74,-40 74,40, body extent -43,-29 43,29, height 57
0805L [mm] "0805 from SM-752 data"
  rect 1.1x1.4 smd: 1(-0.75,0) 2(0.75,0)
  body extent -1.1,-0.72 1.1,0.72, height 1.45
1206 [mm] "1206 from SM-752 data"
  rect 1.3x1.85 smd: 1(-1.45,0) 2(1.45,0)
  silkscreen extent -2.4,-1.21 2.4,1.21, body extent -1.7,-0.9 1.7,0.9, height 1.35
2512L [mm] "Chip Resistor, Body 6.3x3.2mm, IPC High Density"
  rect 1.1x3.3 smd: 1(-2.85,0) 2(2.85,0)
  silkscreen extent -1.9,-1.55 1.9,1.55, body extent -3.22,-1.67 3.22,1.67, height 0.71
5106 [mm] "Keystone"
  rect 0.99x1.4 smd: 1(-0.85,0) 2(0.88,0)
  silkscreen extent -1.63,-0.97 1.65,0.97, body extent -1.06,-0.69 1.06,0.69, height 0.84
AssemblyNote [mil] "Assembly Note"
AssemblyNoteLabel [mil] "Assembly Note for PCB Labels"
CONN_22-05-3041 [mm] "MOLEX"
  rect 1.65x1.65 hole 1.02: 1(-3.81,5.7)
  round 1.65 hole 1.02: 2(-1.27,5.7) 3(1.27,5.7) 4(3.81,5.7)
  silkscreen extent -5,0 5,4.18, body extent -5,-6.91 5,6.02, height 6.37
CONN_PEC02SAAN [mm] "SULLINS"
  rrect7% 1.5x1.5 hole 1.016: 1(-1.27,0)
  round 1.5 hole 1.016: 2(1.27,0)
  silkscreen extent -2.54,-1.52 2.54,1.27, body extent -2.54,-1.27 2.54,1.27, height 8.38
DBV0005A_N [mm] "SOT23, 5-Leads, Body 2.9x1.6mm, Pitch 0.95mm, Lead Span 2.8mm, IPC Medium Density"
  rrect17% 1x0.6 smd: 1(-1.375,0.95) 2(-1.375,0) 3(-1.375,-0.95) 4(1.375,-0.95) 5(1.375,0.95)
  silkscreen extent -1.63,-1.55 0.38,1.55, body extent -1.42,-1.46 1.42,1.46, height 1.09
DQG0008A [mm] "SMD, 8-Leads, Body 3.3x3.3mm, Pitch 0.65mm"
  rrect45% 0.75x0.44 smd paste-0.05 mask-0.05: 1(-1.525,0.975) 2(-1.525,0.325) 3(-1.525,-0.325) 4(-1.525,-0.975) 5(1.525,-0.975) 6(1.525,-0.325) 7(1.525,0.325) 8(1.525,0.975)
  rrect15% 0.676x1.125 on Top Paste: 9(-0.212,0.662) 9(-0.212,-0.663) 9(0.664,0.662) 9(0.664,-0.663)
  rrect6% 1.775x2.45 on Top Solder: 9(0.327,0)
  rrect8% 2.5x2.55 smd paste-1.5 mask-1.5: 9(0.65,0)
  rrect29% 0.5x0.34 on Top Solder: 9(1.175,0.975) 9(1.175,-0.325) 9(1.175,0.325) 9(1.175,-0.975)
  silkscreen extent -1.8,-1.8 1.8,1.8, body extent -1.65,-1.65 1.65,1.65, height 1.1
DRT0003A [mm] "SOTFL, 3-Leads, Body 1x1mm (inc leads), Pitch 0.35mm"
  rect 0.3x0.45 smd: 1(-0.35,-0.575) 2(0.35,-0.575) 3(0,0.575)
  silkscreen extent -0.85,-0.62 0.67,0.58, body extent -0.52,-0.42 0.52,0.42, height 0.5
FCC_disclaimer [mil]
Fiducial10-30 [mm]
  round 1 smd mask+1: 1(0,0)
  Top Layer keep-out circle w1.678: c0,0 r0.75
IHLP-2020BZ [mm] "Vishay Dale recommended land pattern.  Document 34261 rev 12-Sept-13"
  rect 1.915x2.79 smd: 1(-2.037,0) 2(2.037,0)
  silkscreen extent -2.9,-2.7 2.9,2.7, body extent -2.87,-2.72 2.87,2.72, height 2
Keystone5002 [mil] "For Keystone 500x miniature loop terminals"
  round 80 hole 40: 1(0,0)
  silkscreen extent -58,-58 58,58, body extent -49,-49 49,49, height 182
Keystone5004 [mil] "For Keystone 500x miniature loop terminals"
  round 80 hole 40: 1(0,0)
  silkscreen extent -58,-58 58,58, body extent -49,-49 49,49, height 182
Keystone5012#1 [mil] "Keystone Multipurpose loops"
  round 87 hole 63: 1(0,0)
  silkscreen extent -70,-70 70,70, body extent -63,-63 63,62, height 319
Keystone5012#2 [mil] "Keystone Multipurpose loops"
  round 87 hole 63: 1(-40,55)
  silkscreen extent -110,-15 30,125, body extent -103,-8 23,117, height 319
Keystone_1902C [mil] "Hex Standoff, 4-40 threaded, nylon"
  round 1 on Mech4: 0(0,0)
  body extent -145,-126 146,126, height 501
Label_650x200 [mil] "Thermal Transfer Label"
  round 1 on Mech13: 0(0,0)
  silkscreen extent -325,-100 325,100, body extent -325,-100 325,100, height 1
LED_LTST-C190 [mm] "Lite-On"
  rect 0.8x0.8 smd: 1(-0.75,0) 2(0.75,0)
  silkscreen extent -1.1,-0.8 1.8,0.8, body extent -0.85,-0.45 0.85,0.45, height 0.9
Lintes_20-0000016-01 [mm] "Connector, Receptacle, USB Type C, SMT"
  rect 1.1x0.3 smd: 1(3.05,8.44) 3(-3.05,8.44)
  rect 1x0.3 smd: 2(0.07,8.44)
  rect 0.3x0.95 smd: A1(-2.7,7.525) A12(2.85,7.525)
  rect 0.25x0.95 smd: A2(-2.175,7.525) A3(-1.675,7.525) A4(-1.175,7.525) A5(-0.675,7.525) A6(-0.175,7.525) A7(0.325,7.525) A8(0.825,7.525) A9(1.325,7.525) A10(1.825,7.525) A11(2.325,7.525)
  rect 0.3x0.85 smd: B1(2.7,5.875) B12(-2.85,5.875)
  rect 0.25x0.85 smd: B2(2.175,5.875) B3(1.675,5.875) B4(1.175,5.875) B5(0.675,5.875) B6(0.175,5.875) B7(-0.325,5.875) B8(-0.825,5.875) B9(-1.325,5.875) B10(-1.825,5.875) B11(-2.325,5.875)
  oval 1.1x1.7 hole 0.5 slot 1.1 at 90 deg: H1(4.27,6.95) H3(-4.27,6.95)
  oval 1.65x1.1 hole 0.5 slot 1.095 at 0 deg: H2(3.97,6.65) H4(-3.97,6.65)
  round 1.55 hole 0.65: H5(5.7,1.45) H6(-5.7,1.45)
  Keep-Out Layer board cut-out: -4.55,0 -4.55,4.25 -4.767,4.3 -4.941,4.438 -5.037,4.639 -5.037,4.861 -4.941,5.062 -4.767,5.2 -4.55,5.25 -4.55,5.25 -4.55,5.25 4.55,5.25 4.55,5.25 4.767,5.2 4.941,5.062 5.037,4.861 5.037,4.639 4.941,4.438 4.767,4.3 4.55,4.25 4.55,4.25 4.55,0
  silkscreen extent -4.62,8.15 4.62,8.58, body extent -5.8,-1.56 5.8,8.59, height 2.44
Molex_70246-0801 [mm] "Header(shrouded), 2.54mm, 4x2, TH"
  rect 1.65x1.65 hole 1.14: 1(-1.27,3.81)
  round 1.65 hole 1.14: 2(1.27,3.81) 3(-1.27,1.27) 4(1.27,1.27) 5(-1.27,-1.27) 6(1.27,-1.27) 7(-1.27,-3.81) 8(1.27,-3.81)
  silkscreen extent -4.9,-8.89 4.45,8.89, body extent -4.44,-8.89 4.45,8.89, height 9.27
Net-Tie_10milWide_30milLong#1 [mil] "10mil net tie, no solder mask opening, no solder paste"
  rect 30x10 smd paste-5 mask-5: 1(-15,0) 2(15,0)
Net-Tie_10milWide_30milLong#2 [mil] "10mil net tie, no solder mask opening, no solder paste"
  rect 30x10 on Mid3 paste-5 mask-5: 1(-15,0) 2(15,0)
Net-Tie_10milWide_30milLong#3 [mil] "10mil net tie, no solder mask opening, no solder paste"
  rect 15x10 on Mid3 paste-5 mask-5: 1(-15,0) 2(-1,0)
"NY PMS 440 0025 PH" [mm] "4-40 nylon screw and mounting hole"
  round 8 hole 3.2: 1(0,0)
  body extent -3.3,-3.3 3.3,3.3, height 2.69
Pb-Free_Overlay_Small [mil]
  silkscreen extent -46,-46 46,46
PhoenixConact_1727010 [mm]
  rect 1.7x1.7 hole 1.1: 1(-1.905,0)
  round 1.7 hole 1.1: 2(1.905,0)
  silkscreen extent -4.8,-3.6 3.81,3.6, body extent -3.81,-3.6 3.81,3.7, height 8.52
PROBE [mil]
  round 120 hole 73: 1(0,0) 2(100,100) 3(100,-100) 4(-100,-100) 5(-100,100)
RHA0040B [mm] "QFN, 40-Leads, Body 6x6mm, Pitch 0.5mm, Thermal Pad 4.15 x 4.15mm, TI Recommended"
  rrect45% 0.6x0.22 smd mask+0.07: 1(-2.9,2.25) 2(-2.9,1.75) 3(-2.9,1.25) 4(-2.9,0.75) 5(-2.9,0.25) 6(-2.9,-0.25) 7(-2.9,-0.75) 8(-2.9,-1.25) 9(-2.9,-1.75) 10(-2.9,-2.25) 21(2.9,-2.25) 22(2.9,-1.75) 23(2.9,-1.25) 24(2.9,-0.75) 25(2.9,-0.25) 26(2.9,0.25) 27(2.9,0.75) 28(2.9,1.25) 29(2.9,1.75) 30(2.9,2.25)
  rrect45% 0.22x0.6 smd mask+0.07: 11(-2.25,-2.9) 12(-1.75,-2.9) 13(-1.25,-2.9) 14(-0.75,-2.9) 15(-0.25,-2.9) 16(0.25,-2.9) 17(0.75,-2.9) 18(1.25,-2.9) 19(1.75,-2.9) 20(2.25,-2.9) 31(2.25,2.9) 32(1.75,2.9) 33(1.25,2.9) 34(0.75,2.9) 35(0.25,2.9) 36(-0.25,2.9) 37(-0.75,2.9) 38(-1.25,2.9) 39(-1.75,2.9) 40(-2.25,2.9)
  rrect9% 1.17x1.17 on Top Paste: 41(-1.37,-1.37) 41(-1.37,0) 41(-1.37,1.37) 41(0,-1.37) 41(0,0) 41(0,1.37) 41(1.37,-1.37) 41(1.37,0) 41(1.37,1.37)
  rrect2% 4.15x4.15 smd paste-2.1: 41(0,0)
  silkscreen extent -3.22,-3.22 3.22,3.22, body extent -3,-3 3,3, height 1
RSE0010A [mm] "QFN, 10-Leads, Body 1.5x2mm, Pitch 0.5mm, TI Recommended"
  rect 0.55x0.2 smd: 1(-0.675,0.75) 2(-0.675,0.25) 3(-0.675,-0.25) 4(-0.675,-0.75) 6(0.675,-0.75) 7(0.675,-0.25) 8(0.675,0.25) 9(0.675,0.75)
  rect 0.3x0.6 smd: 5(0,-0.9) 10(0,0.9)
  silkscreen extent -1.07,-1.17 0.77,1.18, body extent -0.77,-1.02 0.78,1.03, height 0.61
RTW0024H [mm] "QFN, 24-Leads, Body 4x4mm, Pitch 0.5mm, Thermal Pad 2.7x2.7mm"
  oval 0.6x0.24 smd: 1(-1.9,1.25) 2(-1.9,0.75) 3(-1.9,0.25) 4(-1.9,-0.25) 5(-1.9,-0.75) 6(-1.9,-1.25) 13(1.9,-1.25) 14(1.9,-0.75) 15(1.9,-0.25) 16(1.9,0.25) 17(1.9,0.75) 18(1.9,1.25)
  oval 0.24x0.6 smd: 7(-1.25,-1.9) 8(-0.75,-1.9) 9(-0.25,-1.9) 10(0.25,-1.9) 11(0.75,-1.9) 12(1.25,-1.9) 19(1.25,1.9) 20(0.75,1.9) 21(0.25,1.9) 22(-0.25,1.9) 23(-0.75,1.9) 24(-1.25,1.9)
  rect 2.7x2.7 smd paste-1.35: 25(0,0)
  silkscreen extent -2.22,-2.22 2.22,2.22, body extent -2.07,-2.07 2.07,2.07, height 1.01
Samtec_TSW-103-07-T-S [mm] "Header, 2.54 mm, 3x1, TH"
  rect 1.55x1.55 hole 1.02: 1(-2.54,0)
  round 1.55 hole 1.02: 2(0,0) 3(2.54,0)
  silkscreen extent -3.81,-1.75 3.81,1.27, body extent -3.81,-1.27 3.81,1.27, height 8.39
SMA [mm] "Molded Diode, 2-Leads, Body 4.3x2.6mm, IPC Medium Density, based on OnSemi component dimensions and land pattern"
  rect 2x2 smd: 1(-2,0) 2(2,0)
  silkscreen extent -3.66,-1.57 2.79,1.57, body extent -2.6,-1.3 2.6,1.3, height 2.42
SNT-100-BK-G [mil] "Samtec STEP model"
  round 1 on Mech3: 0(0,0)
  body extent -100,-50 100,50, height 344
SOD-123 [mm] "On Semi recommended land pattern"
  rect 0.915x1.22 smd: 1(-1.637,0) 2(1.637,0)
  silkscreen extent -2.74,-1.17 2.03,1.17, body extent -1.93,-0.9 1.93,0.9, height 1.35
SOD-323 [mm] "NXP recommended land pattern"
  rect 0.6x0.6 smd paste-0.05: 1(-1.1,0) 2(1.1,0)
  silkscreen extent -2.06,-0.86 1.53,0.86, body extent -1.3,-0.67 1.3,0.68, height 1.1
SOT-323 [mm] "Zetex recommended land pattern.  March 2007"
  rect 0.8x0.6 smd: 1(-0.8,0.65) 2(-0.8,-0.65) 3(0.8,0)
  silkscreen extent -1.14,-1.22 0.77,1.22, body extent -1.13,-1.13 1.12,1.12, height 1.13
SW_ADTSM31N [mm] "SMT, 2-Leads, Body 6x3.51mm, Pin Spacing 5.4mm"
  rect 2x1.6 smd: 1(-2.7,0) 2(2.7,0)
  silkscreen extent -3,-1.76 3,1.76, body extent -3.69,-1.75 3.69,1.76, height 4.3
TI_Stacked_SolderMask_Small [mil]
  rect 900x250 smd paste-125 mask-125: 0(0,0)
TRIM_3266W [mm] "Bourns 3266W series REV 08/10"
  rect 1.5x1.5 hole 0.75: 1(0,0)
  round 1.5 hole 0.75: 2(2.54,-2.54) 3(0,-5.08)
  silkscreen extent -1.2,-6.09 3.68,1.01, body extent -1.2,-6.09 3.68,1.01, height 8.45
YFF0009AJAK [mm] "BGA, 9-Balls, Body 1.355x1.38mm, Pitch 0.4mm"
  round 0.23 smd paste-0.13 mask+0.035: A1(-0.4,0.4) A2(0,0.4) A3(0.4,0.4) B1(-0.4,0) B2(0,0) B3(0.4,0) C1(-0.4,-0.4) C2(0,-0.4) C3(0.4,-0.4)
  silkscreen extent -0.81,-0.79 0.79,0.82, body extent -0.69,-0.7 0.69,0.7, height 0.63
YFF0056ACAJ [mm] "BGA, 56-Balls, Body 2.863x3.411mm, Pitch 0.4mm"
  round 0.23 smd paste-0.13 mask+0.038: A1(-1.2,1.4) A2(-0.8,1.4) A3(-0.4,1.4) A4(0,1.4) A5(0.4,1.4) A6(0.8,1.4) A7(1.2,1.4) B1(-1.2,1) B2(-0.8,1) B3(-0.4,1) B4(0,1) B5(0.4,1) B6(0.8,1) B7(1.2,1) C1(-1.2,0.6) C2(-0.8,0.6) C3(-0.4,0.6) C4(0,0.6) C5(0.4,0.6) C6(0.8,0.6) C7(1.2,0.6) D1(-1.2,0.2) D2(-0.8,0.2) D3(-0.4,0.2) D4(0,0.2) D5(0.4,0.2) D6(0.8,0.2) D7(1.2,0.2) E1(-1.2,-0.2) E2(-0.8,-0.2) E3(-0.4,-0.2) E4(0,-0.2) E5(0.4,-0.2) E6(0.8,-0.2) E7(1.2,-0.2) F1(-1.2,-0.6) F2(-0.8,-0.6) F3(-0.4,-0.6) F4(0,-0.6) F5(0.4,-0.6) F6(0.8,-0.6) F7(1.2,-0.6) G1(-1.2,-1) G2(-0.8,-1) G3(-0.4,-1) G4(0,-1) G5(0.4,-1) G6(0.8,-1) G7(1.2,-1) H1(-1.2,-1.4) H2(-0.8,-1.4) H3(-0.4,-1.4) H4(0,-1.4) H5(0.4,-1.4) H6(0.8,-1.4) H7(1.2,-1.4)
  silkscreen extent -1.53,-1.8 1.53,1.81, body extent -1.42,-1.7 1.42,1.7, height 0.63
